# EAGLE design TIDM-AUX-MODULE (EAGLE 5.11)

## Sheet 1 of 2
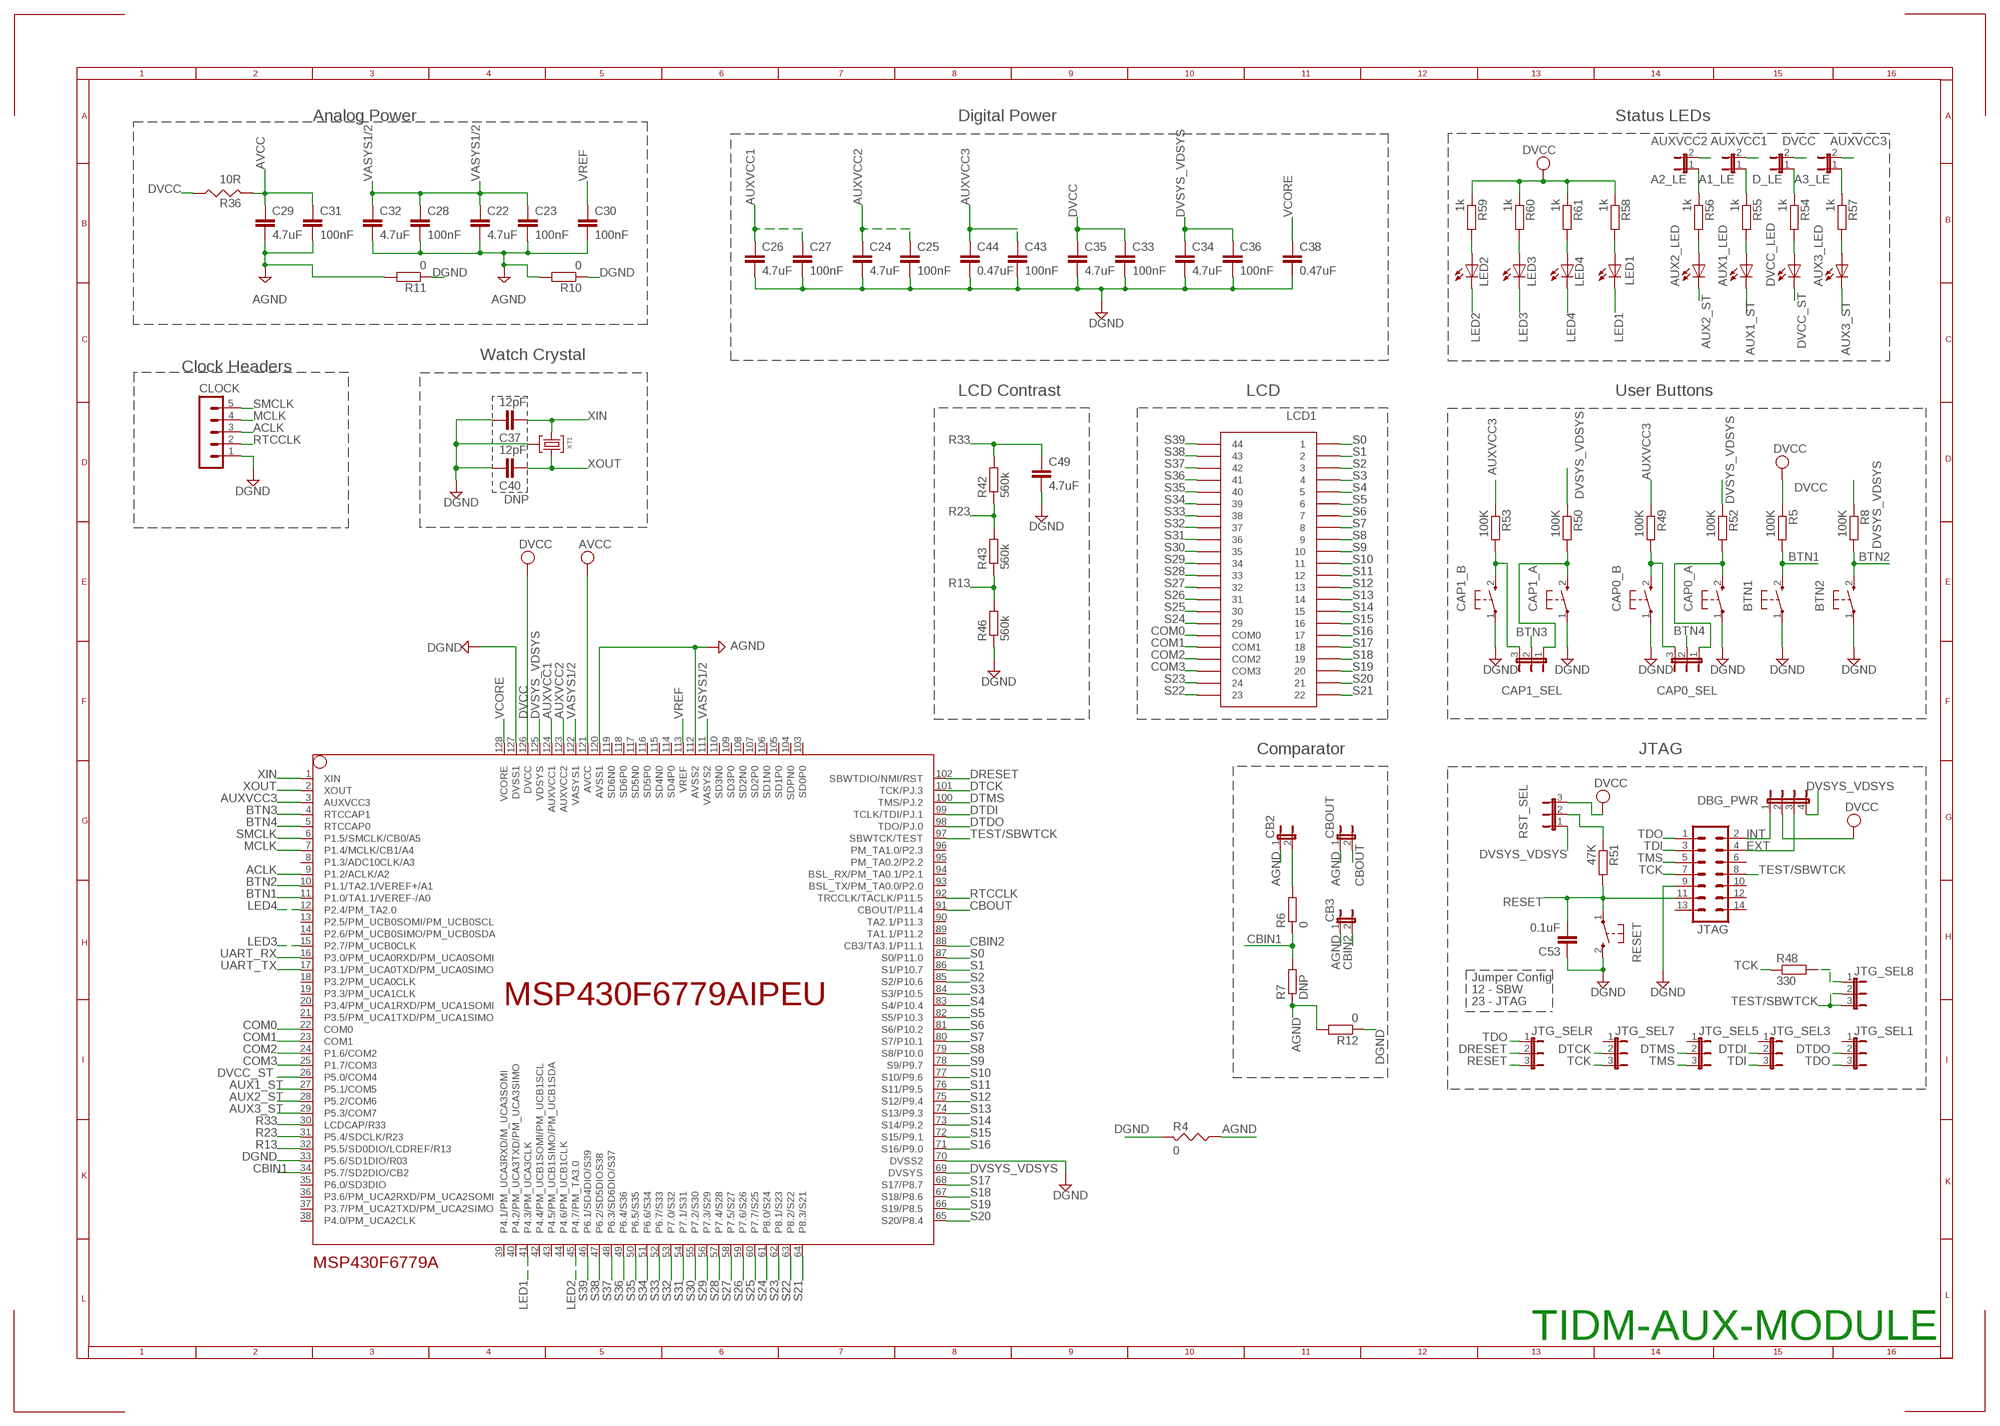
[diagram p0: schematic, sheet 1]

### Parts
A1_LE  JP1E  [JP1]
A2_LE  JP1E  [JP1]
A3_LE  JP1E  [JP1]
AUX1_LED  LED3MM  [LED3MM]
AUX2_LED  LED3MM  [LED3MM]
AUX3_LED  LED3MM  [LED3MM]
BTN1  PB  [PBTH]
BTN2  PB  [PBTH]
C22  4.7uF  C-EUC0603  [C0603]
C23  100nF  C-EUC0603  [C0603]
C24  4.7uF  C-EUC0603  [C0603]
C25  100nF  C-EUC0603  [C0603]
C26  4.7uF  C-EUC0603  [C0603]
C27  100nF  C-EUC0603  [C0603]
C28  100nF  C-EUC0603  [C0603]
C29  4.7uF  C-EUC0603  [C0603]
C30  100nF  C-EUC0603  [C0603]
C31  100nF  C-EUC0603  [C0603]
C32  4.7uF  C-EUC0603  [C0603]
C33  100nF  C-EUC0603  [C0603]
C34  4.7uF  C-EUC0603  [C0603]
C35  4.7uF  C-EUC0603  [C0603]
C36  100nF  C-EUC0603  [C0603]
C37  12pF  C-EUC0603  [C0603]
C38  0.47uF  C-EUC0603  [C0603]
C40  12pF  C-EUC0603  [C0603]
C43  100nF  C-EUC0603  [C0603]
C44  0.47uF  C-EUC0603  [C0603]
C49  4.7uF  C-EUC0603  [C0603]
C53  0.1uF  C-EUC0603  [C0603]
CAP0_A  PB  [PBTH]
CAP0_B  PB  [PBTH]
CAP0_SEL  JP2E  [JP2]
CAP1_A  PB  [PBTH]
CAP1_B  PB  [PBTH]
CAP1_SEL  JP2E  [JP2]
CB2  JP1E  [JP1]
CB3  JP1E  [JP1]
CBOUT  JP1E  [JP1]
CLOCK  MA05-1  [MA05-1]
D_LE  JP1E  [JP1]
DBG_PWR  JP4E  [JP4]
DVCC_LED  LED3MM  [LED3MM]
JTAG  ML14  [ML14]
JTG_SEL1  JP2E  [JP2]
JTG_SEL3  JP2E  [JP2]
JTG_SEL5  JP2E  [JP2]
JTG_SEL7  JP2E  [JP2]
JTG_SEL8  JP2E  [JP2]
JTG_SELR  JP2E  [JP2]
LCD1  TI_160SEG_LCD  [TI_160SEG_LCD]
LED1  LED3MM  [LED3MM]
LED2  LED3MM  [LED3MM]
LED3  LED3MM  [LED3MM]
LED4  LED3MM  [LED3MM]
MSP430F6779A  MSP430F6779AIPEU  [PEU128]
R4  0  RES0805  [R0805]
R5  100K  R-EU_R0603  [R0603]
R6  0  R-EU_R0603  [R0603]
R7  DNP  R-EU_R0603  [R0603]
R8  100K  R-EU_R0603  [R0603]
R10  0  R-EU_R0603  [R0603]
R11  0  R-EU_R0603  [R0603]
R12  0  R-EU_R0603  [R0603]
R36  10R  RES0805  [R0805]
R42  560k  R-EU_R0603  [R0603]
R43  560k  R-EU_R0603  [R0603]
R46  560k  R-EU_R0603  [R0603]
R48  330  R-EU_R0603  [R0603]
R49  100K  R-EU_R0603  [R0603]
R50  100K  R-EU_R0603  [R0603]
R51  47K  R-EU_R0603  [R0603]
R52  100K  R-EU_R0603  [R0603]
R53  100K  R-EU_R0603  [R0603]
R54  1k  R-EU_R0603  [R0603]
R55  1k  R-EU_R0603  [R0603]
R56  1k  R-EU_R0603  [R0603]
R57  1k  R-EU_R0603  [R0603]
R58  1k  R-EU_R0603  [R0603]
R59  1k  R-EU_R0603  [R0603]
R60  1k  R-EU_R0603  [R0603]
R61  1k  R-EU_R0603  [R0603]
RESET  PB  [PBTH]
RST_SEL  JP2E  [JP2]
XT1  CM200T  [CM200T]

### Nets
ACLK: CLOCK.3 MSP430F6779A.9(P1.2/ACLK/A2)
AGND: C22.2 C23.2 C28.2 C29.2 C30.2 C31.2 C32.2 CB2.1 CB3.1 CBOUT.1 MSP430F6779A.112(AVSS2) MSP430F6779A.120(AVSS1) R4.1 R7.1 R10.2 R11.2 R12.2
AUX1_ST: AUX1_LED.K(C) MSP430F6779A.27(P5.1/COM5)
AUX2_ST: AUX2_LED.K(C) MSP430F6779A.28(P5.2/COM6)
AUX3_ST: AUX3_LED.K(C) MSP430F6779A.29(P5.3/COM7)
AUXVCC1: A1_LE.2 C26.1 C27.1 MSP430F6779A.124(AUXVCC1) ; also sheet 2
AUXVCC2: A2_LE.2 C24.1 C25.1 MSP430F6779A.123(AUXVCC2) ; also sheet 2
AUXVCC3: A3_LE.2 C43.1 C44.1 MSP430F6779A.3(AUXVCC3) R49.1 R53.1 ; also sheet 2
AVCC: C29.1 C31.1 MSP430F6779A.121(AVCC) R36.2
BTN1: BTN1.2(S) MSP430F6779A.11(P1.0/TA1.1/VEREF-/A0) R5.2
BTN2: BTN2.2(S) MSP430F6779A.10(P1.1/TA2.1/VEREF+/A1) R8.2
BTN3: CAP1_SEL.2 MSP430F6779A.4(RTCCAP1)
BTN4: CAP0_SEL.2 MSP430F6779A.5(RTCCAP0)
CAP0_OP1: CAP0_B.2(S) CAP0_SEL.3 R49.2
CBIN1: MSP430F6779A.34(P5.7/SD2DIO/CB2) R6.1 R7.2
CBIN2: CB3.2 MSP430F6779A.88(CB3/TA3.1/P11.1)
CBOUT: CBOUT.2 MSP430F6779A.91(CBOUT/P11.4)
COM0: LCD1.COM0 MSP430F6779A.22(COM0)
COM1: LCD1.COM1 MSP430F6779A.23(COM1)
COM2: LCD1.COM2 MSP430F6779A.24(P1.6/COM2)
COM3: LCD1.COM3 MSP430F6779A.25(P1.7/COM3)
DGND: BTN1.1(P) BTN2.1(P) C24.2 C25.2 C26.2 C27.2 C33.2 C34.2 C35.2 C36.2 C37.2 C38.2 C40.2 C43.2 C44.2 C49.2 C53.1 CAP0_A.1(P) CAP0_B.1(P) CAP1_A.1(P) CAP1_B.1(P) CLOCK.1 JTAG.9 MSP430F6779A.33(P5.6/SD1DIO/R03) MSP430F6779A.70(DVSS2) MSP430F6779A.127(DVSS1) R4.2 R10.1 R11.1 R12.1 R46.1 RESET.2(S) XT1.P3 ; also sheet 2
DRESET: JTG_SELR.2 MSP430F6779A.102(SBWTDIO/NMI/RST)
DTCK: JTG_SEL7.2 MSP430F6779A.101(TCK/PJ.3)
DTDI: JTG_SEL3.2 MSP430F6779A.99(TCLK/TDI/PJ.1)
DTDO: JTG_SEL1.2 MSP430F6779A.98(TDO/PJ.0)
DTMS: JTG_SEL5.2 MSP430F6779A.100(TMS/PJ.2)
DVCC: C33.1 C35.1 D_LE.2 DBG_PWR.2 MSP430F6779A.126(DVCC) R5.1 R36.1 R58.1 R59.1 R60.1 R61.1 RST_SEL.3 ; also sheet 2
DVCC_ST: DVCC_LED.K(C) MSP430F6779A.26(P5.0/COM4)
DVSYS_VDSYS: C34.1 C36.1 DBG_PWR.4 MSP430F6779A.69(DVSYS) MSP430F6779A.125(VDSYS) R8.1 R50.1 R52.1 RST_SEL.1 ; also sheet 2
EXT: DBG_PWR.3 JTAG.4
INT: DBG_PWR.1 JTAG.2
LED1: LED1.K(C) MSP430F6779A.41(P4.3/PM_UCA3CLK)
LED2: LED2.K(C) MSP430F6779A.45(P4.7/PM_TA3.0)
LED3: LED3.K(C) MSP430F6779A.15(P2.7/PM_UCB0CLK)
LED4: LED4.K(C) MSP430F6779A.12(P2.4/PM_TA2.0)
MCLK: CLOCK.4 MSP430F6779A.7(P1.4/MCLK/CB1/A4)
N$1: CAP1_B.2(S) CAP1_SEL.3 R53.2
N$3: CAP1_A.2(S) CAP1_SEL.1 R50.2
N$4: AUX2_LED.A R56.2
N$6: CAP0_A.2(S) CAP0_SEL.1 R52.2
N$7: AUX1_LED.A R55.2
N$10: JTG_SEL8.1 R48.2
N$14: CB2.2 R6.2
N$16: R51.1 RST_SEL.2
N$21: LED2.A R59.2
N$23: A2_LE.1 R56.1
N$25: A1_LE.1 R55.1
N$27: LED3.A R60.2
N$29: D_LE.1 R54.1
N$30: DVCC_LED.A R54.2
N$31: A3_LE.1 R57.1
N$36: LED4.A R61.2
N$44: LED1.A R58.2
N$46: AUX3_LED.A R57.2
R13: MSP430F6779A.32(P5.5/SD0DIO/LCDREF/R13) R43.1 R46.2
R23: MSP430F6779A.31(P5.4/SDCLK/R23) R42.1 R43.2
R33: C49.1 MSP430F6779A.30(LCDCAP/R33) R42.2
RESET: C53.2 JTAG.11 JTG_SELR.3 R51.2 RESET.1(P)
RTCCLK: CLOCK.2 MSP430F6779A.92(TRCCLK/TACLK/P11.5)
S0: LCD1.1 MSP430F6779A.87(S0/P11.0)
S1: LCD1.2 MSP430F6779A.86(S1/P10.7)
S2: LCD1.3 MSP430F6779A.85(S2/P10.6)
S3: LCD1.4 MSP430F6779A.84(S3/P10.5)
S4: LCD1.5 MSP430F6779A.83(S4/P10.4)
S5: LCD1.6 MSP430F6779A.82(S5/P10.3)
S6: LCD1.7 MSP430F6779A.81(S6/P10.2)
S7: LCD1.8 MSP430F6779A.80(S7/P10.1)
S8: LCD1.9 MSP430F6779A.79(S8/P10.0)
S9: LCD1.10 MSP430F6779A.78(S9/P9.7)
S10: LCD1.11 MSP430F6779A.77(S10/P9.6)
S11: LCD1.12 MSP430F6779A.76(S11/P9.5)
S12: LCD1.13 MSP430F6779A.75(S12/P9.4)
S13: LCD1.14 MSP430F6779A.74(S13/P9.3)
S14: LCD1.15 MSP430F6779A.73(S14/P9.2)
S15: LCD1.16 MSP430F6779A.72(S15/P9.1)
S16: LCD1.17 MSP430F6779A.71(S16/P9.0)
S17: LCD1.18 MSP430F6779A.68(S17/P8.7)
S18: LCD1.19 MSP430F6779A.67(S18/P8.6)
S19: LCD1.20 MSP430F6779A.66(S19/P8.5)
S20: LCD1.21 MSP430F6779A.65(S20/P8.4)
S21: LCD1.22 MSP430F6779A.64(P8.3/S21)
S22: LCD1.23 MSP430F6779A.63(P8.2/S22)
S23: LCD1.24 MSP430F6779A.62(P8.1/S23)
S24: LCD1.29 MSP430F6779A.61(P8.0/S24)
S25: LCD1.30 MSP430F6779A.60(P7.7/S25)
S26: LCD1.31 MSP430F6779A.59(P7.6/S26)
S27: LCD1.32 MSP430F6779A.58(P7.5/S27)
S28: LCD1.33 MSP430F6779A.57(P7.4/S28)
S29: LCD1.34 MSP430F6779A.56(P7.3/S29)
S30: LCD1.35 MSP430F6779A.55(P7.2/S30)
S31: LCD1.36 MSP430F6779A.54(P7.1/S31)
S32: LCD1.37 MSP430F6779A.53(P7.0/S32)
S33: LCD1.38 MSP430F6779A.52(P6.7/S33)
S34: LCD1.39 MSP430F6779A.51(P6.6/S34)
S35: LCD1.40 MSP430F6779A.50(P6.5/S35)
S36: LCD1.41 MSP430F6779A.49(P6.4/S36)
S37: LCD1.42 MSP430F6779A.48(P6.3/SD6DIO/S37)
S38: LCD1.43 MSP430F6779A.47(P6.2/SD5DIOS38)
S39: LCD1.44 MSP430F6779A.46(P6.1/SD4DIO/S39)
SMCLK: CLOCK.5 MSP430F6779A.6(P1.5/SMCLK/CB0/A5)
TCK: JTAG.7 JTG_SEL7.3 R48.1
TDI: JTAG.3 JTG_SEL3.3
TDO: JTAG.1 JTG_SEL1.3 JTG_SELR.1
TEST/SBWTCK: JTAG.8 JTG_SEL8.2 JTG_SEL8.3 MSP430F6779A.97(SBWTCK/TEST)
TMS: JTAG.5 JTG_SEL5.3
UART_RX: MSP430F6779A.16(P3.0/PM_UCA0RXD/PM_UCA0SOMI) ; also sheet 2
UART_TX: MSP430F6779A.17(P3.1/PM_UCA0TXD/PM_UCA0SIMO) ; also sheet 2
VASYS1/2: C22.1 C23.1 C28.1 C32.1 MSP430F6779A.111(VASYS2) MSP430F6779A.122(VASYS1)
VCORE: C38.1 MSP430F6779A.128(VCORE)
VREF: C30.1 MSP430F6779A.113(VREF)
XIN: C37.1 MSP430F6779A.1(XIN) XT1.P2
XOUT: C40.1 MSP430F6779A.2(XOUT) XT1.P1
Unconnected: JTAG.6 JTAG.10 JTAG.12 JTAG.13 JTAG.14 JTG_SEL1.1 JTG_SEL3.1 JTG_SEL5.1 JTG_SEL7.1 MSP430F6779A.8(P1.3/ADC10CLK/A3) MSP430F6779A.13(P2.5/PM_UCB0SOMI/PM_UCB0SCL) MSP430F6779A.14(P2.6/PM_UCB0SIMO/PM_UCB0SDA) MSP430F6779A.18(P3.2/PM_UCA0CLK) MSP430F6779A.19(P3.3/PM_UCA1CLK) MSP430F6779A.20(P3.4/PM_UCA1RXD/PM_UCA1SOMI) MSP430F6779A.21(P3.5/PM_UCA1TXD/PM_UCA1SIMO) MSP430F6779A.35(P6.0/SD3DIO) MSP430F6779A.36(P3.6/PM_UCA2RXD/PM_UCA2SOMI) MSP430F6779A.37(P3.7/PM_UCA2TXD/PM_UCA2SIMO) MSP430F6779A.38(P4.0/PM_UCA2CLK) MSP430F6779A.39(P4.1/PM_UCA3RXD/M_UCA3SOMI) MSP430F6779A.40(P4.2/PM_UCA3TXD/PM_UCA3SIMO) MSP430F6779A.42(P4.4/PM_UCB1SOMI/PM_UCB1SCL) MSP430F6779A.43(P4.5/PM_UCB1SIMO/PM_UCB1SDA) MSP430F6779A.44(P4.6/PM_UCB1CLK) MSP430F6779A.89(TA1.1/P11.2) MSP430F6779A.90(TA2.1/P11.3) MSP430F6779A.93(BSL_TX/PM_TA0.0/P2.0) MSP430F6779A.94(BSL_RX/PM_TA0.1/P2.1) MSP430F6779A.95(PM_TA0.2/P2.2) MSP430F6779A.96(PM_TA1.0/P2.3) MSP430F6779A.103(SD0P0) MSP430F6779A.104(SDPN0) MSP430F6779A.105(SD1P0) MSP430F6779A.106(SD1N0) MSP430F6779A.107(SD2P0) MSP430F6779A.108(SD2N0) MSP430F6779A.109(SD3P0) MSP430F6779A.110(SD3N0) MSP430F6779A.114(SD4P0) MSP430F6779A.115(SD4N0) MSP430F6779A.116(SD5P0) MSP430F6779A.117(SD5N0) MSP430F6779A.118(SD6P0) MSP430F6779A.119(SD6N0)

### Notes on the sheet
- Analog Power | Digital Power | Status LEDs
- Watch Crystal
- Clock Headers
- LCD Contrast | LCD | User Buttons
- DNP
- Comparator | JTAG
- Jumper Config
- 12 - SBW
- 23 - JTAG
- TIDM-AUX-MODULE

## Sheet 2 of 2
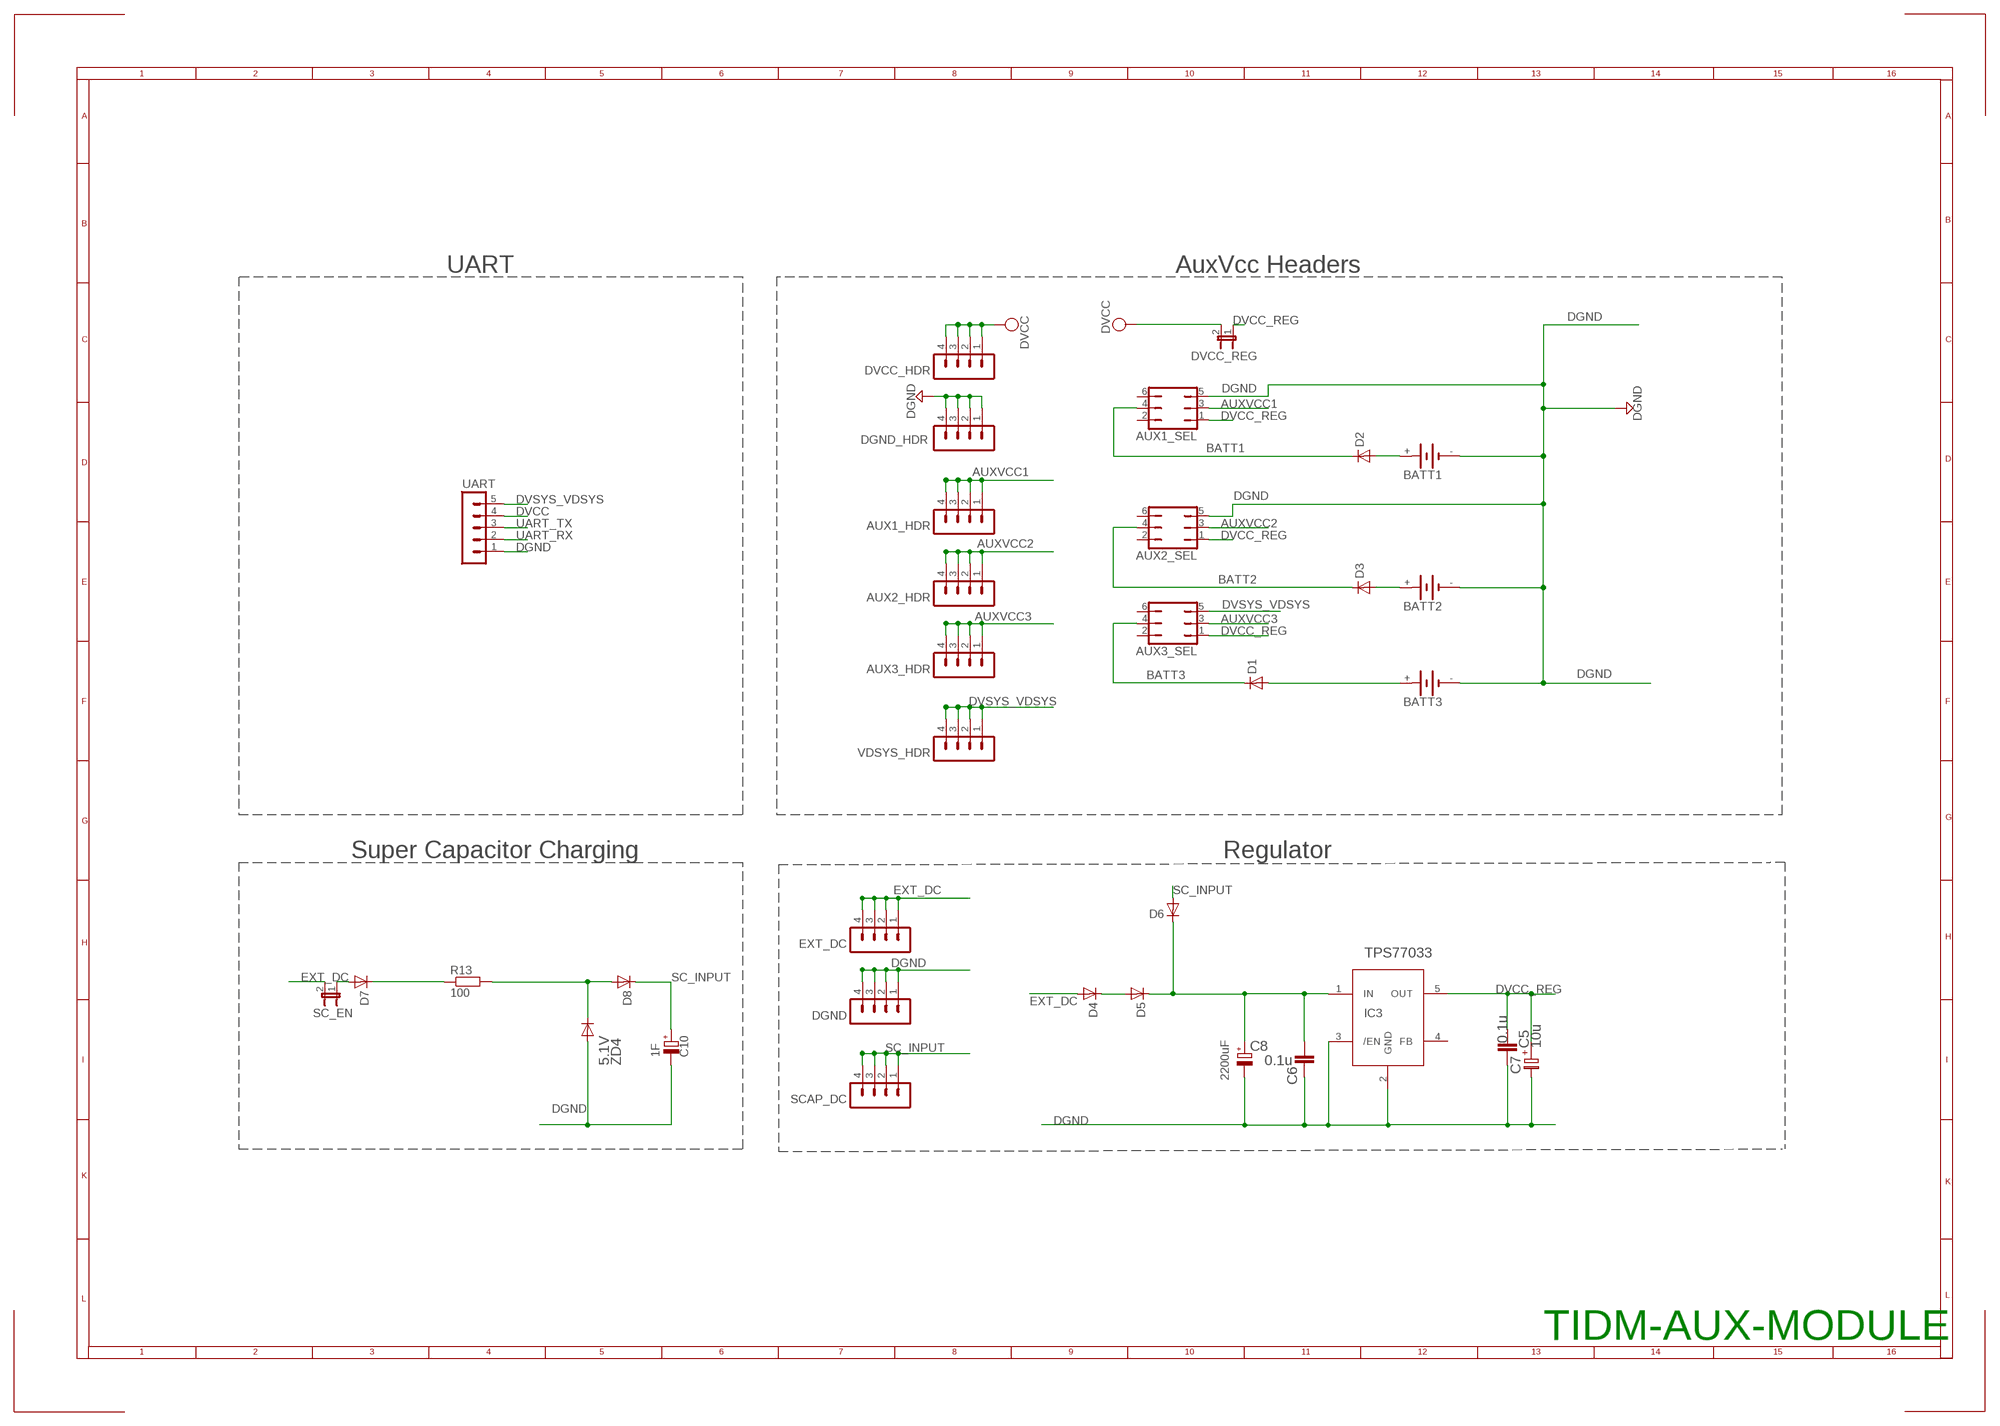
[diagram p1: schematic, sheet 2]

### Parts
AUX1_HDR  MA04-1  [MA04-1]
AUX1_SEL  JP3Q  [JP3Q]
AUX2_HDR  MA04-1  [MA04-1]
AUX2_SEL  JP3Q  [JP3Q]
AUX3_HDR  MA04-1  [MA04-1]
AUX3_SEL  JP3Q  [JP3Q]
BATT1  KS2468NO_HOLES  [KS2468_2]
BATT2  KS2468NO_HOLES  [KS2468_2]
BATT3  KS2468NO_HOLES  [KS2468_2]
C5  10u  ELKO_1210  [1210ELKO]
C6  0.1u  C-EUC0603  [C0603]
C7  0.1u  C-EUC0603  [C0603]
C8  2200uF  CPOL-EUE5-13  [E5-13]
C10  1F  CPOL-EUSUPERCAP  [C050-055X20SUPERCAP]
D1  PMLL4148  [SOD80C]
D2  PMLL4148  [SOD80C]
D3  PMLL4148  [SOD80C]
D4  PMLL4148  [SOD80C]
D5  PMLL4148  [SOD80C]
D6  PMLL4148  [SOD80C]
D7  PMLL4148  [SOD80C]
D8  PMLL4148  [SOD80C]
DGND  MA04-1  [MA04-1]
DGND_HDR  MA04-1  [MA04-1]
DVCC_HDR  MA04-1  [MA04-1]
DVCC_REG  JP1E  [JP1]
EXT_DC  MA04-1  [MA04-1]
IC3  TPS77033  TPS77001  [SOT23/5]
R13  100  R-EU_R0603  [R0603]
SC_EN  JP1E  [JP1]
SCAP_DC  MA04-1  [MA04-1]
UART  MA05-1  [MA05-1]
VDSYS_HDR  MA04-1  [MA04-1]
ZD4  5.1V  D  [SOD-80]

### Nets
AUXVCC1: AUX1_HDR.1 AUX1_HDR.2 AUX1_HDR.3 AUX1_HDR.4 AUX1_SEL.3 ; also sheet 1
AUXVCC2: AUX2_HDR.1 AUX2_HDR.2 AUX2_HDR.3 AUX2_HDR.4 AUX2_SEL.3 ; also sheet 1
AUXVCC3: AUX3_HDR.1 AUX3_HDR.2 AUX3_HDR.3 AUX3_HDR.4 AUX3_SEL.3 ; also sheet 1
BATT1: AUX1_SEL.4 D2.C
BATT2: AUX2_SEL.4 D3.C
BATT3: AUX3_SEL.4 D1.C
DGND: AUX1_SEL.5 AUX2_SEL.5 BATT1.- BATT2.- BATT3.- C5.- C6.1 C7.1 C8.- C10.2(-) DGND.1 DGND.2 DGND.3 DGND.4 DGND_HDR.1 DGND_HDR.2 DGND_HDR.3 DGND_HDR.4 IC3.2(GND) IC3.3(/EN) UART.1 ZD4.1(A) ; also sheet 1
DVCC: DVCC_HDR.1 DVCC_HDR.2 DVCC_HDR.3 DVCC_HDR.4 DVCC_REG.2 UART.4 ; also sheet 1
DVCC_REG: AUX1_SEL.1 AUX2_SEL.1 AUX3_SEL.1 C5.+ C7.2 DVCC_REG.1 IC3.5(OUT)
DVSYS_VDSYS: AUX3_SEL.5 UART.5 VDSYS_HDR.1 VDSYS_HDR.2 VDSYS_HDR.3 VDSYS_HDR.4 ; also sheet 1
EXT_DC: D4.A EXT_DC.1 EXT_DC.2 EXT_DC.3 EXT_DC.4 SC_EN.2
N$2: D4.C D5.A
N$13: D8.A R13.2 ZD4.2(K)
N$15: BATT1.+ D2.A
N$19: BATT2.+ D3.A
N$20: BATT3.+ D1.A
N$22: D7.A SC_EN.1
REG_IN: C6.2 C8.+ D5.C D6.C IC3.1(IN)
SC_INPUT: C10.1(+) D6.A D8.C SCAP_DC.1 SCAP_DC.2 SCAP_DC.3 SCAP_DC.4
SCAP_1: D7.C R13.1
UART_RX: UART.2 ; also sheet 1
UART_TX: UART.3 ; also sheet 1
Unconnected: AUX1_SEL.2 AUX1_SEL.6 AUX2_SEL.2 AUX2_SEL.6 AUX3_SEL.2 AUX3_SEL.6 IC3.4(FB)

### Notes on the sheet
- UART | AuxVcc Headers
- Super Capacitor Charging | Regulator
- TIDM-AUX-MODULE

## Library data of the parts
A1_LE A2_LE A3_LE CB2 CB3 CBOUT D_LE DVCC_REG SC_EN = jumper:JP1E: JUMPER
AUX1_HDR AUX2_HDR AUX3_HDR DGND DGND_HDR DVCC_HDR EXT_DC SCAP_DC VDSYS_HDR = custom_con-lstb:MA04-1: PIN HEADER; OC_FARNELL: unknown; OC_NEWARK: unknown
AUX1_LED AUX2_LED AUX3_LED DVCC_LED LED1-LED4 = led:LED: LED
AUX1_SEL AUX2_SEL AUX3_SEL = jumper:JP3Q: JUMPER
BATT1-BATT3 = _MSP430:KS2468
BTN1 BTN2 CAP0_A CAP0_B CAP1_A CAP1_B RESET = electricalmeter:PB: OMRON SWITCH
C5 = SMD:ELKO_1210
C6 C7 C22-C38 C40 C43 C44 C49 C53 = resistor:C-EU: CAPACITOR, European symbol
C8 = ElecMeter:CPOL-EU: POLARIZED CAPACITOR, European symbol
C10 = rcl:CPOL-EU: POLARIZED CAPACITOR, European symbol
CAP0_SEL CAP1_SEL JTG_SEL1 JTG_SEL3 JTG_SEL5 JTG_SEL7 JTG_SEL8 JTG_SELR RST_SEL = custom_jumper:JP2E: JUMPER
CLOCK UART = con-lstb:MA05-1: PIN HEADER; OC_FARNELL: unknown; OC_NEWARK: unknown
D1-D8 = FE449x EVM:PMLL4148: DIODE
DBG_PWR = jumper:JP4E: JUMPER
IC3 = flash-evk:TPS77001
JTAG = con-ml:ML14: HARTING; OC_FARNELL: unknown; OC_NEWARK: unknown
LCD1 = Personal:TI_160SEG_LCD
MSP430F6779A = Personal:MSP430F6779AIPEU: MSP430F6779IPEU
R4 R36 = _MSP430:RES
R5-R8 R10-R12 R42 R43 R46 R48-R61 = resistor:R-EU_: RESISTOR, European symbol
R13 = rcl:R-EU_: RESISTOR, European symbol
XT1 = F20xx PIR Demo & Eval:CM200T
ZD4 = SMD:D

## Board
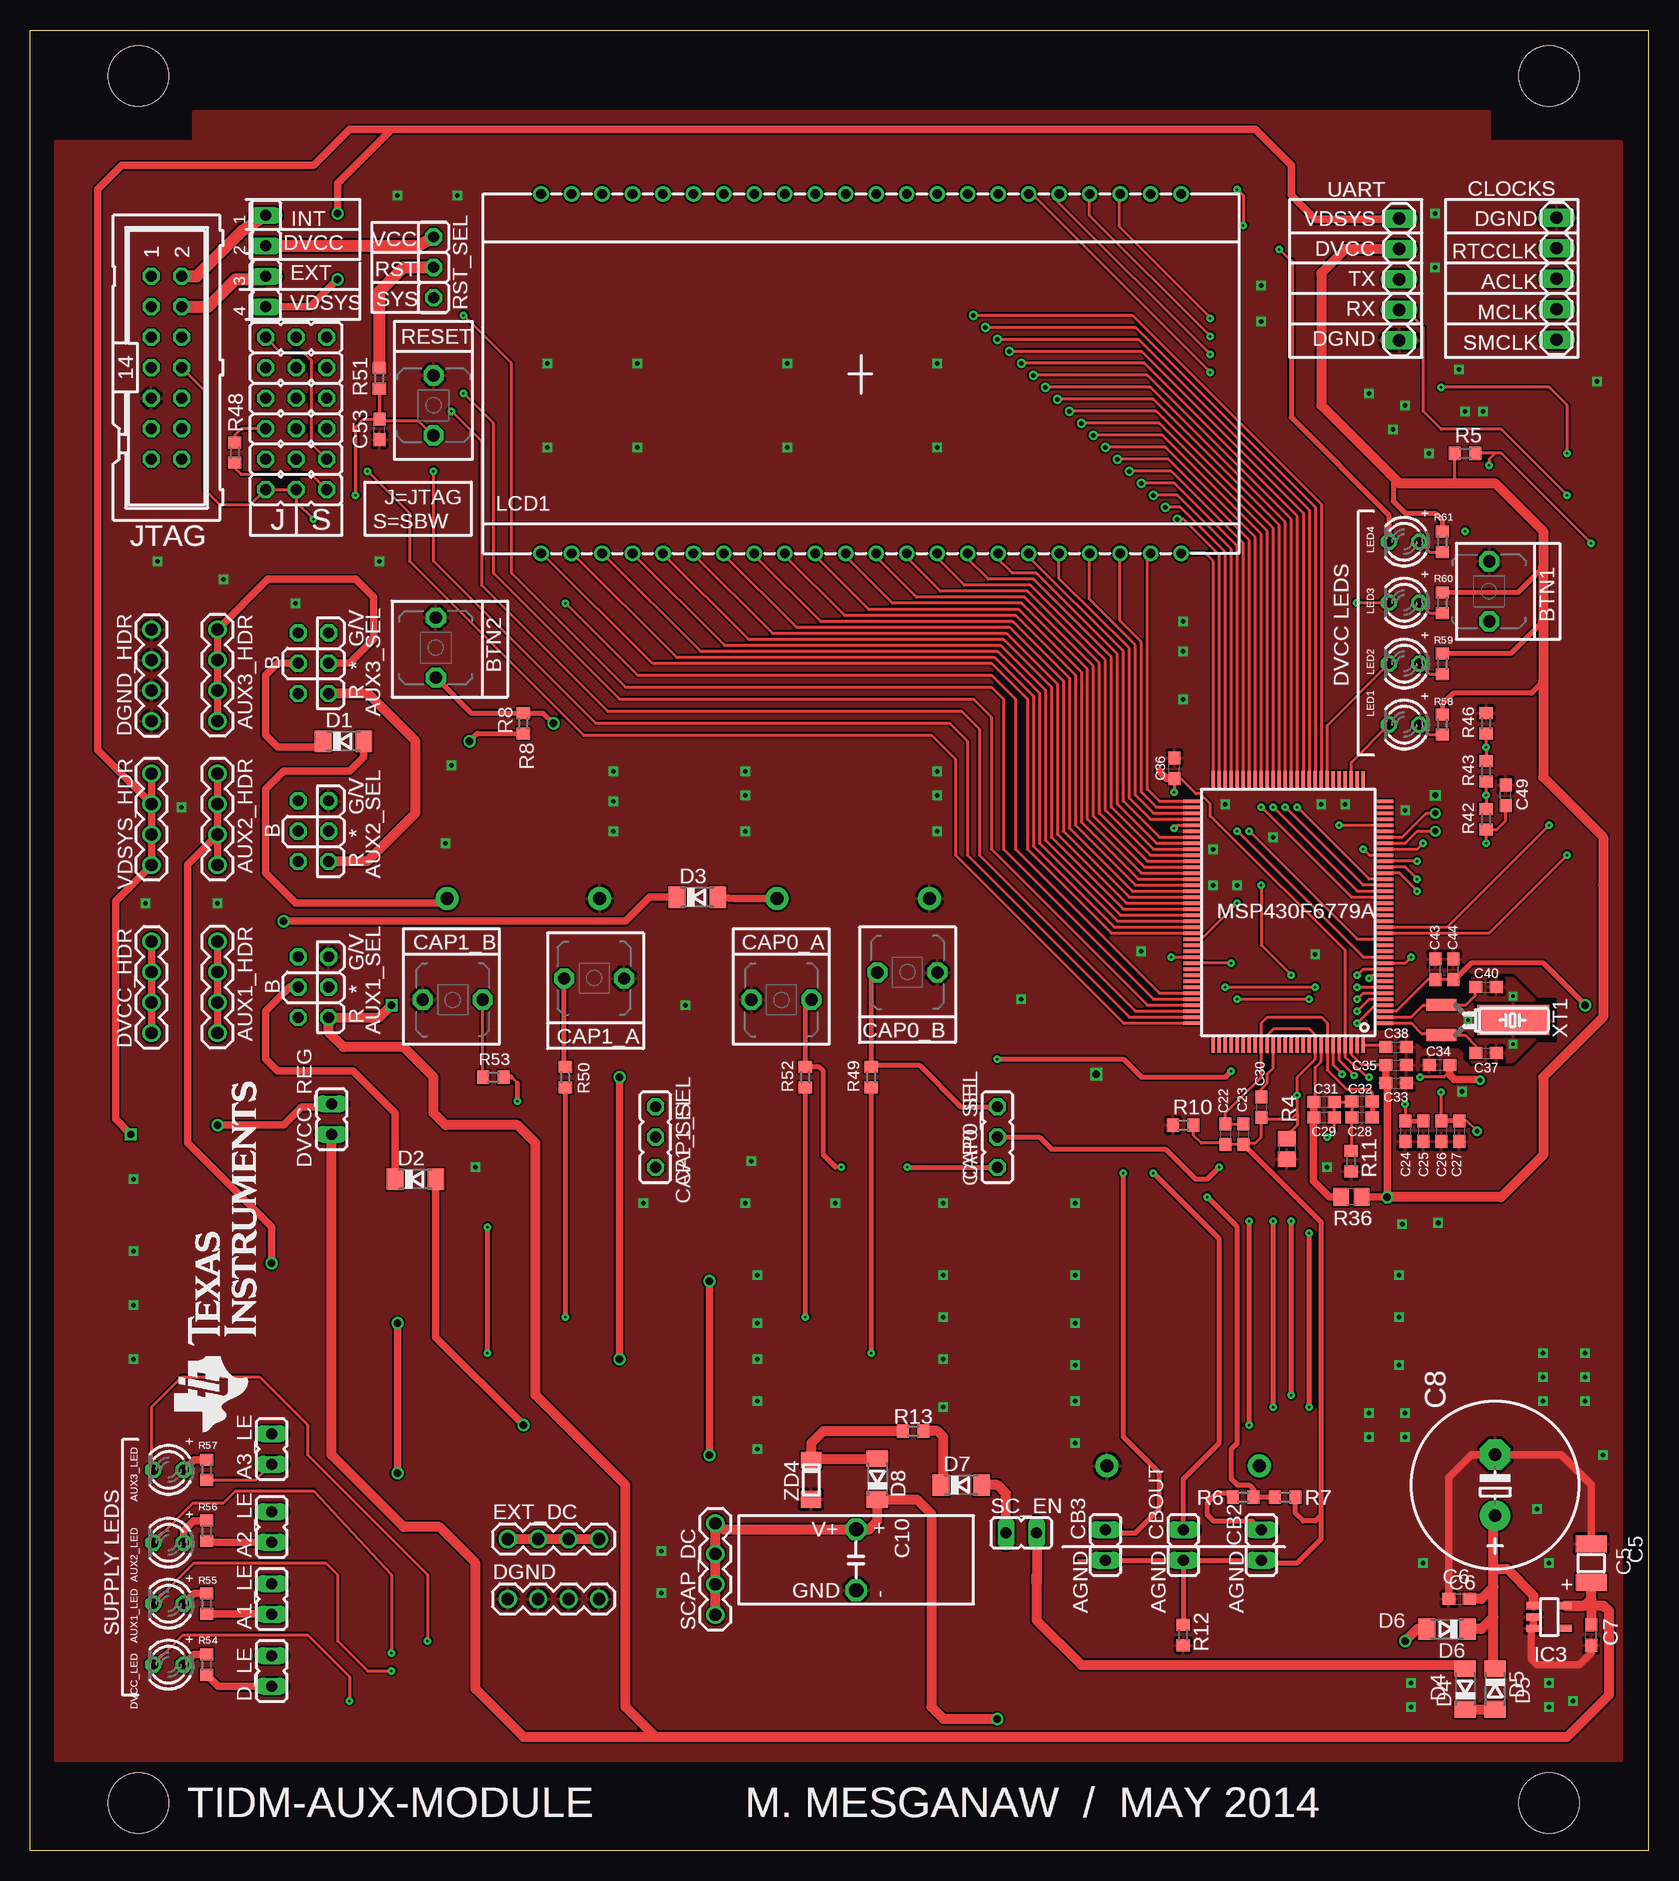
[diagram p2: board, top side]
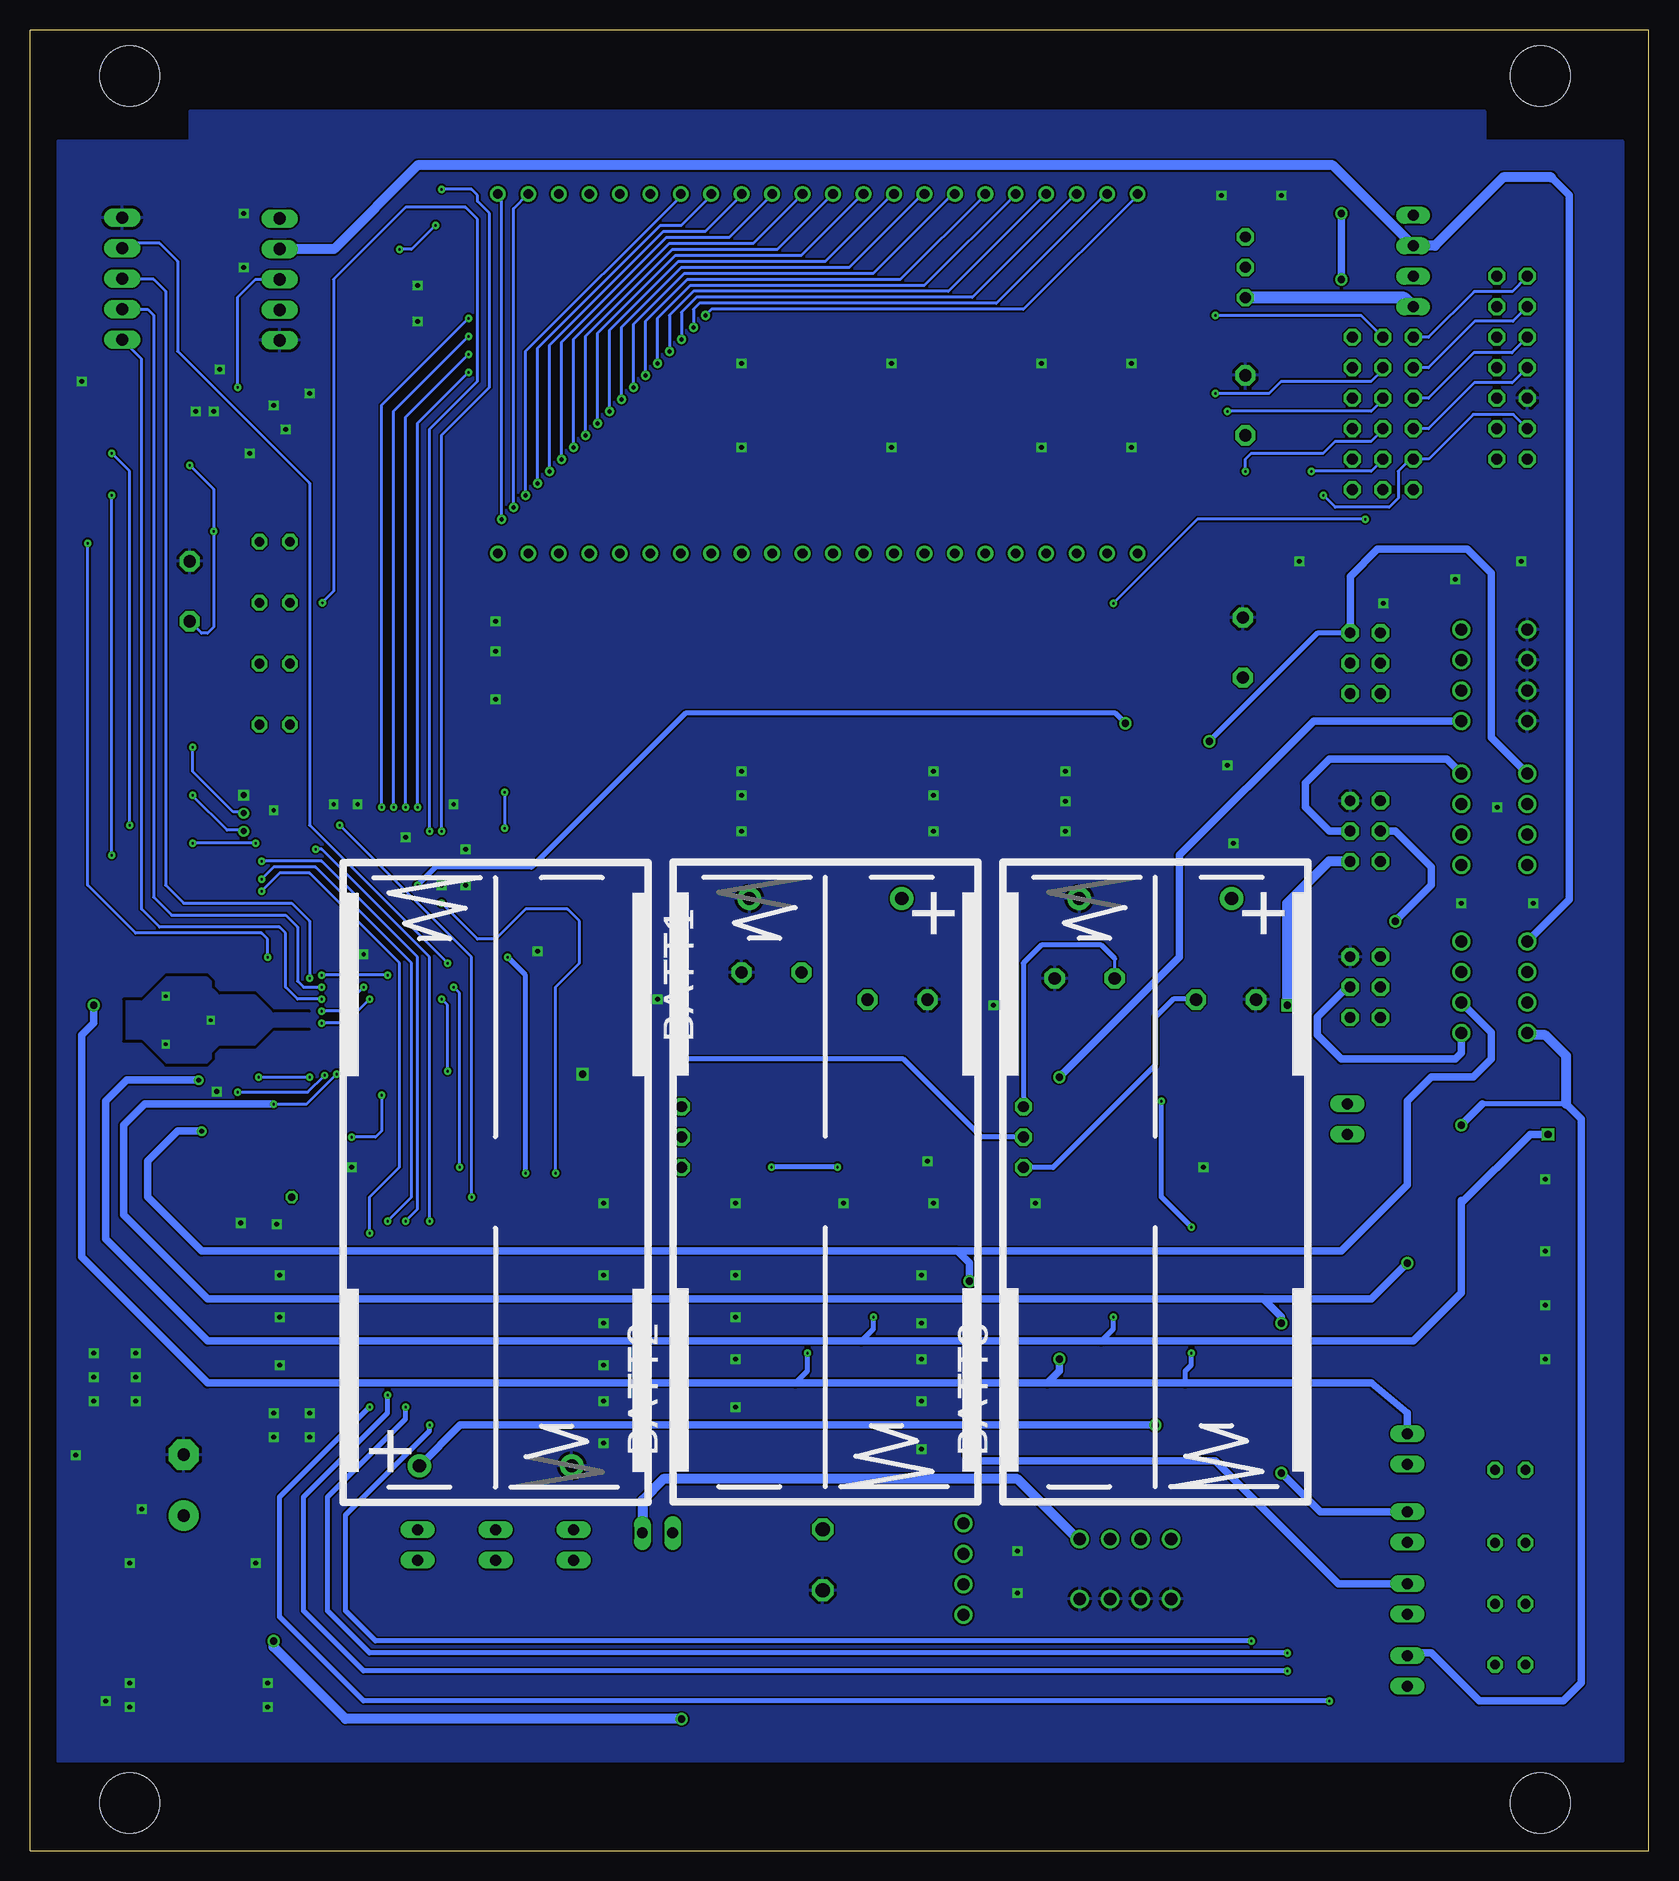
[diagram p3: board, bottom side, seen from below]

Size 134.94 x 151.79 mm. Coordinates in mm from the lower left corner, seen from the top.
Outline: 134.94,0 0,0 0,151.79 134.94,151.79 134.94,0
Copper layers (1*16): Top 0.0356mm / dielectric 1.5011mm / Bottom 0.0356mm
Design rules "typical_4pcb *": minimum track width 10mil, minimum drill 8mil, track to track 6mil, track to pad 6mil, pad to pad 6mil, via to via 6mil, smd to smd 6mil, copper to edge 15mil, drill to drill 8mil, minimum pad ring 10mil, minimum via ring 8mil, stop-mask expansion 4mil, vias tented up to drill 25mil, thermal gap 10mil
Holes 5 mm at 9.04,147.95 126.63,147.95 126.63,4 9.04,4
tRestrict: 20 lines
bRestrict: 19 lines

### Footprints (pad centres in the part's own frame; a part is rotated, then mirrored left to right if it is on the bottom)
JP1 = drill 0.914 long: 1 0,-1.27; 2 0,1.27
MA04-1 = drill 1.016 round: 1 -3.81,0; 2 -1.27,0; 3 1.27,0; 4 3.81,0
LED3MM = drill 0.813 octagon: A -1.27,0; K 1.27,0
JP3Q = drill 0.914 octagon: 1 -2.54,-1.27; 2 -2.54,1.27; 3 0,-1.27; 4 0,1.27; 5 2.54,-1.27; 6 2.54,1.27
KS2468_2 = drill 1.1 pad 1.93 round: + 24.892,-6.35; - 24.892,6.35
PBTH = drill 1.016 pad 1.676 octagon: 1 -0.001,0.001; 2 5.001,0.001
1210ELKO = smd 1.397 x 2.591: + 1.6,0; - -1.6,0
C0603 = smd 1.1 x 1: 1 -0.85,0; 2 0.85,0
E5-13 = drill 1.016 pad 2.54 round: + -2.54,0 | drill 1.016 pad 2.54 octagon: - 2.54,0
C050-055X20SUPERCAP = drill 1.2 octagon: 1 -3.81,-1.27; 2 1.27,-1.27
JP2 = drill 0.914 octagon: 1 -2.54,0; 2 0,0; 3 2.54,0
MA05-1 = drill 1.016 long: 1 -5.08,0; 2 -2.54,0; 3 0,0; 4 2.54,0; 5 5.08,0
SOD80C = smd 1.4 x 1.8: A 1.7,0; C -1.7,0
JP4 = drill 0.914 long: 1 -3.81,0; 2 -1.27,0; 3 1.27,0; 4 3.81,0
SOT23/5 = smd 0.6 x 1.2: 1 -0.95,-1.306; 2 0,-1.306; 3 0.95,-1.306; 4 0.95,1.306; 5 -0.95,1.306
ML14 = drill 0.914 octagon: 1 -7.62,-1.27; 2 -7.62,1.27; 3 -5.08,-1.27; 4 -5.08,1.27; 5 -2.54,-1.27; 6 -2.54,1.27; 7 0,-1.27; 8 0,1.27; 9 2.54,-1.27; 10 2.54,1.27; 11 5.08,-1.27; 12 5.08,1.27; 13 7.62,-1.27; 14 7.62,1.27
TI_160SEG_LCD = drill 0.8 round: 1 4.826,0; 2 7.366,0; 3 9.906,0; 4 12.446,0; 5 14.986,0; 6 17.526,0; 7 20.066,0; 8 22.606,0; 9 25.146,0; 10 27.686,0; 11 30.226,0; 12 32.766,0; 13 35.306,0; 14 37.846,0; 15 40.386,0; 16 42.926,0; 17 45.466,0; 18 48.006,0; 19 50.546,0; 20 53.086,0; 21 55.626,0; 22 58.166,0; 23 58.166,29.972; 24 55.626,29.972; 29 42.926,29.972; 30 40.386,29.972; 31 37.846,29.972; 32 35.306,29.972; 33 32.766,29.972; 34 30.226,29.972; 35 27.686,29.972; 36 25.146,29.972; 37 22.606,29.972; 38 20.066,29.972; 39 17.526,29.972; 40 14.986,29.972; 41 12.446,29.972; 42 9.906,29.972; 43 7.366,29.972; 44 4.826,29.972; COM0 45.466,29.972; COM1 48.006,29.972; COM2 50.546,29.972; COM3 53.086,29.972
PEU128 = smd 0.3 x 1.4: 1 -9,-7.8; 2 -8.5,-7.8; 3 -8,-7.8; 4 -7.5,-7.8; 5 -7,-7.8; 6 -6.5,-7.8; 7 -6,-7.8; 8 -5.5,-7.8; 9 -5,-7.8; 10 -4.5,-7.8; 11 -4,-7.8; 12 -3.5,-7.8; 13 -3,-7.8; 14 -2.5,-7.8; 15 -2,-7.8; 16 -1.5,-7.8; 17 -1,-7.8; 18 -0.5,-7.8; 19 0,-7.8; 20 0.5,-7.8; 21 1,-7.8; 22 1.5,-7.8; 23 2,-7.8; 24 2.5,-7.8; 25 3,-7.8; 26 3.5,-7.8; 27 4,-7.8; 28 4.5,-7.8; 29 5,-7.8; 30 5.5,-7.8; 31 6,-7.8; 32 6.5,-7.8; 33 7,-7.8; 34 7.5,-7.8; 35 8,-7.8; 36 8.5,-7.8; 37 9,-7.8; 38 9.5,-7.8; 65 9.5,8.3; 66 9,8.3; 67 8.5,8.3; 68 8,8.3; 69 7.5,8.3; 70 7,8.3; 71 6.5,8.3; 72 6,8.3; 73 5.5,8.3; 74 5,8.3; 75 4.5,8.3; 76 4,8.3; 77 3.5,8.3; 78 3,8.3; 79 2.5,8.3; 80 2,8.3; 81 1.5,8.3; 82 1,8.3; 83 0.5,8.3; 84 0,8.3; 85 -0.5,8.3; 86 -1,8.3; 87 -1.5,8.3; 88 -2,8.3; 89 -2.5,8.3; 90 -3,8.3; 91 -3.5,8.3; 92 -4,8.3; 93 -4.5,8.3; 94 -5,8.3; 95 -5.5,8.3; 96 -6,8.3; 97 -6.5,8.3; 98 -7,8.3; 99 -7.5,8.3; 100 -8,8.3; 101 -8.5,8.3; 102 -9,8.3 | smd 1.4 x 0.3: 39 11.3,-6; 40 11.3,-5.5; 41 11.3,-5; 42 11.3,-4.5; 43 11.3,-4; 44 11.3,-3.5; 45 11.3,-3; 46 11.3,-2.5; 47 11.3,-2; 48 11.3,-1.5; 49 11.3,-1; 50 11.3,-0.5; 51 11.3,0; 52 11.3,0.5; 53 11.3,1; 54 11.3,1.5; 55 11.3,2; 56 11.3,2.5; 57 11.3,3; 58 11.3,3.5; 59 11.3,4; 60 11.3,4.5; 61 11.3,5; 62 11.3,5.5; 63 11.3,6; 64 11.3,6.5; 103 -10.8,6.5; 104 -10.8,6; 105 -10.8,5.5; 106 -10.8,5; 107 -10.8,4.5; 108 -10.8,4; 109 -10.8,3.5; 110 -10.8,3; 111 -10.8,2.5; 112 -10.8,2; 113 -10.8,1.5; 114 -10.8,1; 115 -10.8,0.5; 116 -10.8,0; 117 -10.8,-0.5; 118 -10.8,-1; 119 -10.8,-1.5; 120 -10.8,-2; 121 -10.8,-2.5; 122 -10.8,-3; 123 -10.8,-3.5; 124 -10.8,-4; 125 -10.8,-4.5; 126 -10.8,-5; 127 -10.8,-5.5; 128 -10.8,-6
R0805 = smd 1.3 x 1.5: 1 -0.85,0; 2 0.85,0
R0603 = smd 1 x 1.1: 1 -0.85,0; 2 0.85,0
CM200T = smd 1 x 2.5: P1 -1.25,-5; P2 1.25,-5 | smd 2.5 x 6: P3 0,1
SOD-80 = smd 1.397 x 1.702: 1 1.397,-0.025; 2 -1.88,0

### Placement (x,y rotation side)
A1_LE  20.13,21 0 top
A2_LE  20.13,27 0 top
A3_LE  20.13,33.5 0 top
AUX1_HDR  15.63,72 270 top
AUX1_LED  11.55,20.61 180 top
AUX1_SEL  23.63,72 90 top
AUX2_HDR  15.63,86 270 top
AUX2_LED  11.55,25.69 180 top
AUX2_SEL  23.63,85 90 top
AUX3_HDR  15.63,98 270 top
AUX3_LED  11.55,31.77 180 top
AUX3_SEL  23.63,99 90 top
BATT1  96.13,57 270 bottom
BATT2  68.63,54.5 90 bottom
BATT3  41.13,54.5 90 bottom
BTN1  121.63,107.5 270 top
BTN2  33.83,102.8 270 top
C5  130.13,24 270 top
C6  119.13,21 0 top
C7  130.13,18 90 top
C8  122.13,30.5 90 top
C10  70.13,23 270 top
C22  99.63,59.75 270 top
C23  101.13,59.75 270 top
C24  114.63,60 270 top
C25  116.13,60 270 top
C26  117.63,60 270 top
C27  119.13,60 270 top
C28  111.03,61.12 180 top
C29  107.88,61.15 0 top
C30  102.63,62 270 top
C31  107.88,62.45 0 top
C32  111.02,62.46 180 top
C33  113.88,64 0 top
C34  117.51,65.5 180 top
C35  113.88,65.5 0 top
C36  95.38,90.25 90 top
C37  121.38,66.5 0 top
C38  113.88,67 0 top
C40  121.38,72 0 top
C43  117.13,73.5 90 top
C44  118.63,73.5 90 top
C49  123.01,88 90 top
C53  29.13,118.5 90 top
CAP0_A  60.13,70.96 0 top
CAP0_B  75.63,73.24 180 top
CAP0_SEL  80.63,59.5 90 top
CAP1_A  49.52,72.74 180 top
CAP1_B  32.74,70.96 0 top
CAP1_SEL  52.13,59.5 270 top
CB2  102.63,25.5 0 top
CB3  89.63,25.5 0 top
CBOUT  96.13,25.5 0 top
CLOCK  127.25,131.06 270 top
D1  26.13,92.5 0 top
D2  32.13,56 0 top
D3  55.63,79.5 0 top
D4  119.63,13.5 90 top
D5  122.13,13.5 270 top
D6  118.13,18.5 180 top
D7  77.63,30.5 0 top
D8  70.63,31 90 top
D_LE  20.13,15 0 top
DBG_PWR  19.64,132.53 270 top
DGND  43.63,21 0 top
DGND_HDR  10.13,98 90 top
DVCC_HDR  10.13,72 90 top
DVCC_LED  11.55,15.53 180 top
DVCC_REG  25.13,61 0 top
EXT_DC  43.63,26 0 top
IC3  126.63,19.5 270 top
JTAG  11.39,123.64 270 top
JTG_SEL1  22.18,126.18 180 top
JTG_SEL3  22.18,123.64 180 top
JTG_SEL5  22.18,121.1 180 top
JTG_SEL7  22.18,118.56 180 top
JTG_SEL8  22.18,113.48 180 top
JTG_SELR  22.18,116.02 180 top
LCD1  37.78,108.16 0 top
LED1  114.55,93.89 180 top
LED2  114.55,98.97 180 top
LED3  114.55,104.05 180 top
LED4  114.55,109.13 180 top
MSP430F6779A  105.13,78 90 top
R4  104.76,58.53 270 top
R5  119.63,116.5 0 top
R6  101.13,29.5 180 top
R7  104.63,29.5 180 top
R8  41.13,94 90 top
R10  96.13,60.5 0 top
R11  110.13,57.5 90 top
R12  96.13,18 90 top
R13  73.63,35 180 top
R36  110.14,54.51 180 top
R42  121.38,86 270 top
R43  121.38,90 270 top
R46  121.38,94 270 top
R48  17.07,116.56 270 top
R49  70.13,64.5 90 top
R50  44.63,64.5 90 top
R51  29.13,122.75 270 top
R52  64.63,64.5 90 top
R53  38.63,64.5 180 top
R54  14.73,15.53 90 top
R55  14.73,20.61 90 top
R56  14.73,26.69 90 top
R57  14.73,31.77 90 top
R58  117.73,93.89 270 top
R59  117.73,98.97 270 top
R60  117.73,104.05 270 top
R61  117.73,109.13 270 top
RESET  33.63,118 90 top
RST_SEL  33.63,132 90 top
SC_EN  82.63,26.5 270 top
SCAP_DC  57.13,23.5 90 top
UART  114.13,131 90 top
VDSYS_HDR  10.13,86 270 top
XT1  122.63,69.25 270 top
ZD4  65.13,30.7 270 top

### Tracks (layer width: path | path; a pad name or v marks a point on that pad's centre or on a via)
ACLK  (via drill 0.2)
  Top 0.254: MSP430F6779A.9 111.88,73 v111.63,72.75
  Bottom 0.254: v111.63,72.75 111.63,77.5 113.13,79 122.13,79 123.63,80.5 123.63,130 124.63,131 127.19,131 CLOCK.3 127.14,130.95
AGND  (via drill 0.2)
  Top 0.254: 87.36,24.23 CB3.1 | 102.13,24.23 102.36,24 | 105.63,61.5 v105.63,63 105.63,64.5 107.13,66 MSP430F6779A.120 107.13,68 106.63,68.5 103.63,68.5 103.13,68 MSP430F6779A.112 | 105.63,61.5 105.13,61 102.78,61 C30.2 102.63,59.5 102.13,59 101.23,59 C23.2 C22.2 99.53,59 97.63,59 96.98,59.65 R10.2 | R4.1 104.76,59.63 105.63,60.5 105.63,61.5 | v108.13,59.5 108.73,60.1 C29.2 C31.2 C32.2 C28.2 110.13,61.08 R11.2
  Top 0.406: CBOUT.1 102.13,24.23 CB2.1 | CB3.1 CBOUT.1 | C23.2 107.63,52.4 107.63,28 | 107.63,28 107.63,26 105.63,24 102.36,24 | R7.1 105.48,28.15 106.13,27.5 107.13,27.5 107.63,28 | CBOUT.1 R12.2
  Bottom 0.254: v105.63,63 105.63,60 106.13,59.5 v108.13,59.5
AUX1_ST  (via drill 0.2)
  Top 0.254: MSP430F6779A.27 114.63,82 v115.63,81 | AUX1_LED.K 13.67,24 24.63,24 25.63,23 25.63,17.5 28.13,15 v30.13,15
  Top 0.406: v105.13,38 v105.13,52.5
  Bottom 0.254: v115.63,81 114.63,82 111.13,82 103.13,74 103.13,54.5 v105.13,52.5
  Bottom 0.406: v105.13,38 105.13,36.5 112.13,29.5 112.13,20 107.13,15 v30.13,15
AUX2_ST  (via drill 0.2)
  Top 0.254: v115.63,82.5 MSP430F6779A.28 | v30.13,16.5 30.13,23 23.63,30 17.13,30 16.13,29 13.59,29 AUX2_LED.K 12.59,28
  Top 0.406: v103.63,37 v103.63,52.5
  Bottom 0.254: v103.63,52.5 102.63,53.5 102.63,74.5 110.63,82.5 v115.63,82.5
  Bottom 0.406: v103.63,37 103.63,36 110.13,29.5 110.13,20 106.63,16.5 v30.13,16.5
AUX3_ST  (via drill 0.2)
  Top 0.254: MSP430F6779A.29 111.63,83 v111.13,83.5 | v33.13,17.5 33.13,23 23.13,33 23.13,35.5 19.13,39.5 12.63,39.5 10.13,37 10.13,31.92 AUX3_LED.K
  Top 0.406: v101.63,35.5 v101.63,52.5
  Bottom 0.254: v101.63,52.5 101.63,74.5 110.63,83.5 v111.13,83.5
  Bottom 0.406: v101.63,35.5 101.63,35 108.63,28 108.63,20 106.13,17.5 v33.13,17.5
AUXVCC1  (via drill 0.2, 0.4, 0.6)
  Top 0.254: MSP430F6779A.124 109.13,65.9 v110.38,64.65 | C26.1 v117.63,63.25 | C27.1 119.78,60.85 v120.63,60
  Top 0.406: C26.1 117.63,60.5 117.98,60.85 C27.1
  Top 0.61: AUX1_HDR.1 AUX1_HDR.2 AUX1_HDR.3 AUX1_HDR.4 | v56.63,33 v56.63,47.5
  Bottom 0.254: v117.63,63.25 111.78,63.25 v110.38,64.65
  Bottom 0.61: AUX1_HDR.4 15.63,66.5 16.13,66 25.63,66 27.63,68 27.63,69.5 25.13,72 AUX1_SEL.3 | v120.63,60 122.63,60 125.13,57.5 125.13,54.5 120.63,50 57.63,50 | A1_LE.2 25.9,22.27 36.13,32.5 56.13,32.5 v56.63,33 | v56.63,47.5 56.63,49 57.63,50 | 57.63,50 25.63,50 20.13,55.5 20.13,62.5 18.13,64.5 14.63,64.5 13.13,66 13.13,68.23 AUX1_HDR.3
AUXVCC2  (via drill 0.2, 0.6)
  Top 0.254: MSP430F6779A.123 108.63,65.5 v109.38,64.75 | v114.63,62.25 C24.1
  Top 0.406: C24.1 114.63,61 114.78,60.85 C25.1
  Top 0.61: AUX2_HDR.1 AUX2_HDR.2 AUX2_HDR.3 | AUX2_HDR.3 AUX2_HDR.4 | v30.63,31.5 v30.63,44 | v20.13,49 20.13,52 13.13,59 13.13,82.23 AUX2_HDR.3
  Bottom 0.254: v114.63,62.25 111.88,62.25 v109.38,64.75
  Bottom 0.61: AUX2_SEL.3 26.63,85 28.63,87 28.63,89 26.63,91 16.82,91 AUX2_HDR.1 | v114.63,62.25 125.38,62.25 127.13,60.5 127.13,53 120.13,46 32.13,46 | A2_LE.2 27.4,28.27 v30.63,31.5 | v30.63,44 30.63,44.5 32.13,46 | 32.13,46 23.13,46 v20.13,49
AUXVCC3  (via drill 0.2, 0.6)
  Top 0.254: C43.1 117.26,72.62 | MSP430F6779A.3 113.88,70 116.53,72.65 C43.1 | C43.1 117.13,72.5 117.28,72.65 C44.1 | 40.63,64 40.13,64.5
  Top 0.406: C44.1 118.78,72.65 120.13,74 126.13,74 v129.63,70.5 | v70.13,41.5 R49.1 | v38.13,41.5 v38.13,52 | 40.13,64.5 R53.1 | v40.63,62.5 40.63,64
  Top 0.61: AUX3_HDR.4 AUX3_HDR.3 AUX3_HDR.2 AUX3_HDR.1 19.82,106 27.13,106 28.63,104.5 28.63,101 26.63,99 AUX3_SEL.3 | v49.13,41 v49.13,64.5
  Bottom 0.406: v70.13,41.5 70.13,40 71.13,39 | v40.63,62.5 40.63,54.5 v38.13,52 | v38.13,41.5 38.13,40.5 38.63,40 38.63,39
  Bottom 0.61: v129.63,70.5 129.63,69 130.63,68 130.63,49.5 120.13,39 71.13,39 50.13,39 | 50.13,39 38.63,39 23.13,39 20.13,36.5 A3_LE.2 | AUX3_HDR.4 27.94,94.19 39.13,83 39.13,74.5 v49.13,64.5 | v49.13,41 49.13,40 50.13,39
AVCC
  Top 0.254: 106.88,61.25 106.98,61.15 C29.1 | 107.13,62.5 107.08,62.45 C31.1 | MSP430F6779A.121 107.63,65.83 107.13,65.33 107.13,62.45 C31.1 | C31.1 106.93,62.45 106.88,62.5 107.03,62.65
  Top 0.406: C29.1 107.13,61.25 107.03,61.35
  Top 0.61: 107.03,61.35 C31.1 | 106.98,61.15 106.98,55.85 108.32,54.51 R36.2
BATT1
  Top 0.61: AUX1_SEL.4 21.63,72 19.63,70 19.63,66 20.63,65 26.93,65 30.43,61.5 D2.C
BATT2  (via drill 0.6)
  Top 0.61: v21.13,77.5 49.63,77.5 51.63,79.5 D3.C
  Bottom 0.61: AUX2_SEL.4 21.13,85 18.13,82 18.13,80.5 v21.13,77.5
BATT3
  Top 0.61: AUX3_SEL.4 20.63,99 19.63,98 19.63,93 20.63,92 23.93,92 D1.C
BTN1  (via drill 0.2)
  Top 0.254: MSP430F6779A.11 114.63,74 v115.13,74.5 | 122.13,116.5 122.63,116.5 v130.13,109 | 122.13,116.5 R5.2 | v121.63,115.5 121.63,116 122.13,116.5
  Bottom 0.254: v115.13,74.5 115.13,76 115.63,76.5 126.13,76.5 130.13,80.5 v130.13,109 | 122.13,103 BTN1.2 120.63,101.5 120.13,101.5 119.63,102 v119.63,110 119.63,113.5 v121.63,115.5
BTN2  (via drill 0.2, 0.6)
  Top 0.254: MSP430F6779A.10 111.13,73.5 v110.63,73 | v102.63,80.5 102.63,75.5 v105.13,73
  Top 0.406: BTN2.2 | BTN2.2 36.78,94.85 R8.2 42.78,94.85 v43.63,94
  Bottom 0.254: v105.13,73 v110.63,73
  Bottom 0.406: v102.63,80.5 101.13,82 93.13,82 80.28,94.85 44.48,94.85 v43.63,94
BTN3  (via drill 0.2)
  Top 0.254: MSP430F6779A.4 112.13,70.5 v110.63,69 | v100.63,71 v106.63,71
  Top 0.406: v100.13,65 99.63,64.5 92.63,64.5 91.13,66 v80.63,66
  Bottom 0.254: v110.63,69 108.63,69 v106.63,71 | v100.63,71 100.13,70.5 v100.13,65
  Bottom 0.406: CAP1_SEL.2 55.63,59.5 62.13,66 v80.63,66
BTN4  (via drill 0.2)
  Top 0.254: MSP430F6779A.5 111.63,71 v110.63,70 | v99.63,72 v107.13,72
  Top 0.406: v99.13,57 98.13,56 97.13,56 94.63,58.5 85.13,58.5 84.13,59.5 CAP0_SEL.2
  Bottom 0.254: v110.63,70 109.13,70 v107.13,72 | v99.63,72 99.13,71.5 v99.13,57
CAP0_OP1
  Top 0.254: R49.2 70.28,65.5
  Top 0.406: R49.2 70.13,72.74 CAP0_B.2 | CAP0_SEL.3 77.59,62.04 74.13,65.5 70.28,65.5
CBIN1  (via drill 0.2)
  Top 0.254: v109.13,85.5 MSP430F6779A.34
  Top 0.406: R7.2 R6.1 101.98,30.15 101.63,30.5 100.63,30.5 100.13,31 100.13,33.5 100.63,34 100.63,52 v98.13,54.5
  Bottom 0.254: v98.13,54.5 98.13,74.5 v109.13,85.5
CBIN2  (via drill 0.2)
  Top 0.254: MSP430F6779A.88 97.63,76 v100.63,79
  Top 0.406: v91.13,56.5 91.13,34.5 94.13,31.5 94.13,28.5 92.13,26.5 89.9,26.5 CB3.2
  Bottom 0.254: v100.63,79 97.63,76 96.13,76 93.63,78.5 90.13,78.5 89.13,77.5 89.13,74 91.13,72 v91.13,56.5
CBOUT  (via drill 0.2)
  Top 0.254: v95.13,74.5 MSP430F6779A.91
  Top 0.406: v93.63,56.5 99.13,51 99.13,34 96.13,31 CBOUT.2
  Bottom 0.406: v95.13,74.5 93.63,73 v93.63,56.5
COM0  (via drill 0.2)
  Top 0.254: MSP430F6779A.22 110.13,79.5 v102.63,87 | LCD1.COM0 83.51,138.13 v98.38,123.25
  Bottom 0.254: v102.63,87 102.63,119 v98.38,123.25
COM1  (via drill 0.2)
  Top 0.254: MSP430F6779A.23 110.63,80 v103.63,87 | v98.38,124.75 98.38,124.77 85.75,137.41 85.75,138.09 LCD1.COM1
  Bottom 0.254: v103.63,87 103.63,119.5 v98.38,124.75
COM2  (via drill 0.2)
  Top 0.254: MSP430F6779A.24 111.13,80.5 v104.63,87 | LCD1.COM2 88.33,136.31 v98.38,126.25
  Bottom 0.254: v104.63,87 104.63,120 v98.38,126.25
COM3  (via drill 0.2)
  Top 0.254: MSP430F6779A.25 111.63,81 v105.63,87 | v98.38,127.75 98.38,127.82 90.83,135.37 90.83,138.09 LCD1.COM3
  Bottom 0.254: v105.63,87 105.63,120.5 v98.38,127.75
DGND  (via drill 0.3, 0.36, 0.4, 0.5, 0.6)
  Top 0.254: BTN2.1 33.83,102.7 33.63,102.5
  Top 0.61: C7.1 130.13,16.5 129.13,15.5 125.63,15.5 125.13,16 125.13,18.36 IC3.3 IC3.2 | C5.- 130.13,30.5 127.63,33 122.17,33 C8.- 122.09,33 120.13,33 118.28,31.15 C6.1
  other vias: 99.63,87.25 117.13,88 130.63,122.5 92.63,75 121.13,120 111.63,121.5 88.88,64.75 119.88,69.25 123.63,71.25 123.63,67.25 114.63,86.75 107.63,87.25 96.13,102.5 96.13,100 75.63,124 63.13,124 50.63,124 114.38,52.25 117.38,52.35 75.63,117 63.13,117 50.63,117 119.38,63.3 116.63,116.5 113.63,118.5 114.63,120.5 43.13,124 43.13,117 29.13,107.5 10.63,107.5 22.13,104 34.63,84 48.63,85 96.13,96 59.63,90 75.63,90 54.63,70.5 82.63,71 59.63,54 67.13,54 76.13,54 87.13,54 51.13,54 30.63,138 35.63,138 8.63,50 15.63,79 9.63,79 16.13,106 37.13,57 60.13,57.5 114.13,48 87.13,48 76.13,48 60.63,48 60.63,44 60.63,41 60.63,37.5 60.63,33.5 76.13,44.5 76.13,41 76.13,37 87.13,44 87.13,40.5 87.13,37.5 87.13,34 114.13,44.5 114.13,40.5 126.13,39.5 126.13,37.5 129.63,37.5 111.63,34.5 129.63,39.5 111.63,36.5 114.63,36.5 126.13,41.5 114.63,34.5 129.63,41.5 52.63,25 52.63,21.5 8.63,45.5 8.63,41 102.63,130.5 102.63,127.5 117.13,136.5 119.13,123.5 117.13,132 48.63,90 35.13,90.5 12.63,87 8.63,56 98.63,80.5 100.63,80.5 98.63,83.5 103.63,84.5 109.63,87.25 107.13,74.75 108.13,57 119.63,120 115.13,12 115.13,14 126.63,12 126.63,14 116.13,24 131.13,33 126.63,24 128.63,12.5 125.63,28.5 59.63,85 75.63,85 48.63,87.5 59.63,88 75.63,88
  pour Top: 2.13,142.5 13.63,142.5 13.63,145 121.63,145 121.63,142.5 132.63,142.5 132.63,7.5 2.13,7.5
  pour Bottom: 2.13,142.5 13.63,142.5 13.63,145 121.63,145 121.63,142.5 132.63,142.5 132.63,7.5 2.13,7.5
DRESET  (via drill 0.2)
  Top 0.254: MSP430F6779A.102 91.13,69 77.13,83 77.13,91 75.13,93 46.13,93 31.63,107.5 31.63,111.5 v28.13,115
  Bottom 0.254: JTG_SELR.2 22.18,115.95 23.13,115 v28.13,115
DTCK  (via drill 0.2)
  Top 0.254: MSP430F6779A.101 91.63,69.5 78.13,83 78.13,92.5 76.63,94 47.13,94 33.63,107.5 v33.63,115
  Bottom 0.254: JTG_SEL7.2 22.18,118.45 23.13,117.5 26.13,117.5 27.13,116.5 33.13,116.5 33.63,116 v33.63,115
DTDI  (via drill 0.2)
  Top 0.254: MSP430F6779A.99 93.13,70.5 80.13,83.5 80.13,94.5 78.63,96 49.13,96 38.63,106.5 38.63,119 v36.13,121.5
  Bottom 0.254: JTG_SEL3.2 22.18,123.45 23.13,122.5 30.63,122.5 31.63,121.5 v36.13,121.5
DTDO  (via drill 0.2)
  Top 0.254: MSP430F6779A.98 93.63,71 81.13,83.5 81.13,96 80.13,97 49.63,97 40.13,106.5 40.13,124 v36.13,128
  Bottom 0.254: v36.13,128 24,128 JTG_SEL1.2
DTMS  (via drill 0.2)
  Top 0.254: MSP430F6779A.100 92.13,70 79.13,83 79.13,93.5 77.63,95 49.63,95 49.13,95 48.13,95 37.63,105.5 37.63,117.5 v35.13,120
  Bottom 0.254: JTG_SEL5.2 22.18,120.95 23.13,120 v35.13,120
DVCC  (via drill 0.6)
  Top 0.254: MSP430F6779A.126 110.13,66.4 111.03,65.5 C35.1 | 113.38,114.75 113.63,114.5 | R5.1 118.78,114.15 118.63,114
  Top 0.3: 131.13,80.5 130.98,80.35
  Top 0.406: 112.63,64 C33.1 113.13,63.9 | R60.1 124.03,104.9 126.13,107 | R59.1 123.45,99.82 126.13,102.5 | R58.1 117.73,95.59 118.63,96.5 125.13,96.5 126.13,97.5 | R61.1 117.73,110.91 117.13,111.5 114.63,111.5 113.63,112.5 113.63,114.5
  Top 0.61: 113.13,63.9 v113.13,54.5 R36.1 | C33.1 C35.1 | DVCC_HDR.1 DVCC_HDR.2 DVCC_HDR.3 DVCC_HDR.4 | v15.63,60.5 21.13,60.5 22.63,62 24.86,62 DVCC_REG.2
  Top 0.679: 122.68,54.54 122.63,54.5
  Top 0.813: 122.68,54.54 126.13,58 126.13,64.5 131.13,69.5 131.13,80.5 131.13,84.5 126.13,89.5 126.13,97.5 126.13,102.5 126.13,107 126.13,110 122.13,114 118.63,114 114.13,114 113.38,114.75 107.63,120.5 107.63,131.54 109.63,133.54 UART.4 | R36.1 | 113.18,54.54 v113.13,54.5 122.63,54.5
  Top 1.016: DBG_PWR.2 32.39,133.8 RST_SEL.3
  Bottom 0.406: 6.9,62.27 13.86,62.27
  Bottom 0.61: 8.13,139.5 6.63,138 6.63,79.31 DVCC_HDR.4 | 6.9,62.27 5.63,61 5.63,14 7.13,12.5 14.13,12.5 18.13,16.5 19.9,16.5 D_LE.2 | 13.86,62.27 v15.63,60.5
  Bottom 0.813: UART.4 109.59,133.54 102.63,140.5 26.34,140.5 DBG_PWR.2 17.83,133.8 12.13,139.5 8.13,139.5 | 6.9,62.27 6.9,66.27 8.63,68 9.94,68 DVCC_HDR.1
DVCC_REG  (via drill 0.6)
  Top 0.813: 130.13,21 129.58,20.45 IC3.5 131.18,20.45 131.63,20 131.63,13 128.13,9.5 52.13,9.5 | 130.13,21 C5.+ | 130.13,21 C7.2 | 52.13,9.5 41.13,9.5 37.13,13.5 37.13,24 34.13,27 31.13,27 25.13,33 DVCC_REG.1 | 52.13,9.5 49.63,12 49.63,30.5 42.13,38 42.13,59 40.63,60.5 34.63,60.5 33.63,61.5 33.63,64.5 31.13,67 26.13,67 24.9,68.23 AUX1_SEL.1 29.09,69.46 v30.13,70.5 | AUX3_SEL.1 28.17,96.46 32.13,92.5 32.13,86.5 28.13,82.5 24.94,82.5 AUX2_SEL.1
  Bottom 0.813: v30.13,70.5 30.13,79 26.63,82.5 24.94,82.5 AUX2_SEL.1
DVCC_ST  (via drill 0.2)
  Top 0.254: MSP430F6779A.26 114.13,81.5 v115.63,80 | v26.63,12.5 26.63,14.5 23.13,18 12.75,18 DVCC_LED.K
  Top 0.406: v106.63,37 v106.63,51.5
  Bottom 0.254: v115.63,80 114.13,81.5 111.63,81.5 104.13,74 104.13,57 106.63,54.5 v106.63,51.5
  Bottom 0.406: v106.63,37 114.13,29.5 114.13,19.5 107.13,12.5 v26.63,12.5
DVSYS_VDSYS  (via drill 0.2, 0.4, 0.6)
  Top 0.254: v95.38,88.25 C36.1 95.41,89.38 95.93,89.38 97.18,88.13 97.53,88.13 98.4,87.27 98.4,86.25 99.13,85.51 99.13,85.5 109.63,75.07 MSP430F6779A.125 109.63,66.15 111.48,64.5 v111.63,64.5 | MSP430F6779A.69 95.63,85.5 v95.38,85.25 | v115.88,64.5 117.86,64.5 118.36,65
  Top 0.406: v44.63,44.5 R50.1 | v64.63,44.5 R52.1 | R8.1 37.28,93.15 v36.63,92.5
  Top 0.61: VDSYS_HDR.2 VDSYS_HDR.1 | VDSYS_HDR.2 VDSYS_HDR.3 VDSYS_HDR.4 7.13,79.19 7.13,61 v8.4,59.73 | DBG_PWR.4 23.35,128.72 v25.63,131 | VDSYS_HDR.2 5.63,91.77 5.63,138.5 7.63,140.5 23.63,140.5 26.63,143.5 30.13,143.5 | C36.1 94.73,89.4 94.13,90 | UART.5 114.05,136 107.13,136 105.13,138 105.13,140.5 102.13,143.5 30.13,143.5 | v25.63,136.5 25.63,139 30.13,143.5 | C34.1 118.36,65 118.36,64.67 118.73,64.3 120.83,64.3 v120.88,64.25
  Bottom 0.254: v95.38,88.25 v95.38,85.25 | v115.88,64.5 v111.63,64.5 | AUX3_SEL.5 24.94,101.5
  Bottom 0.406: v44.63,44.5 44.63,43.5 45.63,42.5 | v64.63,44.5 64.63,43.5 65.63,42.5 | 24.94,101.5 27.63,101.5 v36.63,92.5
  Bottom 0.61: AUX3_SEL.5 24.9,106.23 22.63,108.5 15.13,108.5 13.13,106.5 13.13,92.81 VDSYS_HDR.1 | v25.63,136.5 v25.63,131 | v120.88,64.25 126.88,64.25 128.63,62.5 128.63,51 120.13,42.5 65.63,42.5 45.63,42.5 19.63,42.5 15.63,46.5 15.63,54 | 15.63,54 15.63,54.23 | v8.4,59.73 9.9,59.73 15.63,54
  Bottom 1.016: RST_SEL.1 20.38,129.46 DBG_PWR.4
EXT
  Top 1.016: JTAG.4 14.85,128.72 17.13,131 19.38,131 DBG_PWR.3
EXT_DC
  Top 0.813: 83.9,22.3 83.9,19.23 87.63,15.5 119.33,15.5 D4.A | 83.9,22.3 83.9,23 | 83.9,22.3 83.93,22.3 83.93,26.5 SC_EN.2 | EXT_DC.1 EXT_DC.2 EXT_DC.3 EXT_DC.4
  Bottom 0.813: SC_EN.2 83.9,29.23 82.13,31 52.63,31 47.63,26 EXT_DC.4
INT
  Top 1.016: JTAG.2 13.89,131.26 17.7,135.07 DBG_PWR.1
LED1
  Top 0.254: MSP430F6779A.41 110.13,90.74 LED1.K
LED2
  Top 0.254: MSP430F6779A.45 108.13,93.82 LED2.K
LED3  (via drill 0.2)
  Top 0.254: v101.63,85 110.63,76 MSP430F6779A.15 | v110.58,104.05 LED3.K
  Bottom 0.254: v101.63,85 101.63,118.5 97.63,122.5 97.63,136 98.63,137 103.63,137 109.63,131 109.63,105 v110.58,104.05
LED4  (via drill 0.2)
  Top 0.254: v100.63,85 111.13,74.5 MSP430F6779A.12 | v104.13,133.5 105.13,132.5 | v101.13,135.5 101.13,138 v100.63,138.5
  Top 0.406: LED4.K 113.28,111.35 105.13,119.5 105.13,132.5
  Bottom 0.254: v100.63,85 100.63,118 96.63,122 96.63,136.5 97.63,137.5 97.63,138 98.13,138.5 v100.63,138.5 | v104.13,133.5 103.13,133.5 v101.13,135.5
MCLK  (via drill 0.2)
  Top 0.254: v110.63,72 MSP430F6779A.7
  Bottom 0.254: v110.63,72 112.13,72 112.63,72.5 112.63,77 113.63,78 123.13,78 124.63,79.5 124.63,128 125.13,128.5 127.23,128.5 CLOCK.4 127.02,128.3
N$1
  Top 0.254: CAP1_B.2 37.74,64.54 R53.2
  Bottom 0.254: CAP1_B.2 37.78,71
  Bottom 0.406: CAP1_SEL.3 49.67,56.96 41.13,65.5 41.13,69.5 39.63,71 37.78,71
N$2
  Top 0.813: D4.C D5.A
N$3
  Top 0.254: R50.2 44.52,65.46
  Top 0.406: 44.52,65.46 CAP1_A.2
  Bottom 0.254: CAP1_A.2 44.52,74.39
  Bottom 0.406: 44.52,74.39 45.63,75.5 50.63,75.5 52.13,74 CAP1_SEL.1
N$4
  Top 0.61: AUX2_LED.A 12.82,26.69 13.63,27.5 14.69,27.5 R56.2
N$6  (via drill 0.2)
  Top 0.254: v73.13,57 73.17,56.96 | v67.63,57 67.13,57
  Top 0.406: CAP0_A.2 64.63,70.46 R52.2 65.78,65.35 66.13,65 66.13,58 67.13,57 | 73.17,56.96 CAP0_SEL.1
  Bottom 0.406: v67.63,57 v73.13,57
N$7
  Top 0.61: R55.2 13.67,21.46 AUX1_LED.A
N$10
  Top 0.254: JTG_SEL8.1 23.45,114.75 17.6,114.75 17.07,115.28 R48.2
N$13
  Top 0.813: R13.2 66.13,35 65.13,34 ZD4.2 65.25,32.7 D8.A
N$14
  Top 0.254: 100.13,29.85 R6.2 | 101.9,27.5 CB2.2
  Top 0.406: 100.13,29.85 98.98,29.85 98.13,29 98.13,28 98.63,27.5 101.9,27.5
N$15  (via drill 0.6)
  Top 0.61: D2.A 33.83,42.8 v41.13,35.5
  Bottom 0.61: v41.13,35.5 99.09,35.5 BATT1.+
N$16
  Top 1.016: R51.1 29.13,130 31.13,132 RST_SEL.2
N$19
  Top 0.61: BATT2.+ 58.72,79.39 D3.A
N$20
  Top 0.61: D1.A 27.83,91.2 26.63,90 21.13,90 19.63,88.5 19.63,81.5 22.13,79 34.39,79 BATT3.+
N$21
  Top 0.254: R59.2 116.67,98.12 LED2.A
N$22
  Top 0.813: SC_EN.1 81.36,29.77 80.63,30.5 D7.A
N$23
  Top 0.61: A2_LE.1 15.62,25.73 R56.1
N$25
  Top 0.61: R55.1 20.1,19.76 A1_LE.1
N$27
  Top 0.254: R60.2 116.67,103.2 LED3.A
N$29
  Top 0.61: D_LE.1 15.68,13.73 R54.1
N$30
  Top 0.61: R54.2 13.67,16.38 DVCC_LED.A
N$31
  Top 0.254: R57.1 18.82,30.92 A3_LE.1
N$36
  Top 0.254: R61.2 116.67,108.28 LED4.A
N$44
  Top 0.254: R58.2 116.67,93.04 LED1.A
N$46
  Top 0.61: R57.2 13.67,32.62 AUX3_LED.A
R13  (via drill 0.2, 0.5)
  Top 0.254: MSP430F6779A.32 114.38,84.5 115.88,86 115.88,86.01 116.38,86.5 v117.13,86.5 | R46.2 v121.38,92 R43.1
  Bottom 0.254: v121.38,92 121.38,89.98 118,86.61 117.24,86.61 v117.13,86.5
R23  (via drill 0.2, 0.5)
  Top 0.254: MSP430F6779A.31 114.63,84 115.63,85 v117.13,85 | R43.2 v121.38,88 R42.1
  Bottom 0.254: v121.38,88 121.38,87.95 118.51,85.08 117.21,85.08 v117.13,85
R33  (via drill 0.2)
  Top 0.254: MSP430F6779A.30 115.63,83.5 v116.13,84 | v121.38,84 R42.2 122.28,85.15 123.01,85.88 C49.1
  Bottom 0.254: v116.13,84 v121.38,84
REG_IN
  Top 0.813: D5.C 121.98,15.35 121.98,19.5 | 121.98,19.5 121.98,22 | 121.98,22 121.98,23.5 | 121.98,23.5 121.98,27.81 C8.+ | IC3.1 125.33,21.31 123.13,23.5 121.98,23.5 | D6.C 120.98,18.5 121.98,19.5 | C6.2 120.98,21 121.98,22
RESET  (via drill 0.2)
  Top 0.254: C53.2 29.12,119.75 | RESET.1 33.6,118 32.37,119.24 29.25,119.24 C53.2 | C53.2 27.78,119.35 27.13,118.7 27.13,118
  Top 0.305: C53.2 R51.2 | v27.13,113 27.13,118
  Bottom 0.254: v27.13,113 26.13,112 21.63,112 20.88,112.75 20.88,115 19.86,116.02 JTG_SELR.3 18.36,116.02 14.64,119.74 | JTAG.11 10.12,118.58 11.28,119.74 14.64,119.74 | 14.64,119.74 14.64,119.75
RTCCLK  (via drill 0.2 pad 0.25)
  Top 0.254: v100.13,74 MSP430F6779A.92
  Bottom 0.254: v100.13,74 111.63,85.5 111.63,114 122.63,125 122.63,132.5 124.13,134 126.86,134 CLOCK.2
S0
  Top 0.254: MSP430F6779A.87 90.13,76.5 83.13,83.5 83.13,96 80.13,99 51.86,99 42.71,108.16 LCD1.1
S1
  Top 0.254: MSP430F6779A.86 90.38,77 83.63,83.75 83.63,96.25 80.38,99.5 53.88,99.5 45.23,108.16 LCD1.2
S2
  Top 0.254: MSP430F6779A.85 90.63,77.5 84.13,84 84.13,96.5 80.63,100 55.88,100 47.73,108.16 LCD1.3
S3
  Top 0.254: MSP430F6779A.84 90.88,78 84.63,84.25 84.63,96.75 80.88,100.5 57.88,100.5 LCD1.4
S4
  Top 0.254: MSP430F6779A.83 91.13,78.5 85.13,84.5 85.13,97 81.13,101 59.88,101 52.77,108.12 LCD1.5
S5
  Top 0.254: MSP430F6779A.82 91.38,79 85.63,84.75 85.63,97.25 81.38,101.5 61.88,101.5 55.31,108.08 LCD1.6
S6
  Top 0.254: MSP430F6779A.81 91.63,79.5 86.13,85 86.13,97.5 81.63,102 63.88,102 57.85,108.04 LCD1.7
S7
  Top 0.254: MSP430F6779A.80 91.88,80 86.63,85.25 86.63,97.75 81.88,102.5 65.88,102.5 60.39,108 LCD1.8
S8
  Top 0.254: MSP430F6779A.79 92.13,80.5 87.13,85.5 87.13,98 82.13,103 67.88,103 62.93,107.96 LCD1.9
S9
  Top 0.254: MSP430F6779A.78 92.38,81 87.63,85.75 87.63,98.25 82.38,103.5 69.88,103.5 65.47,107.92 LCD1.10
S10
  Top 0.254: MSP430F6779A.77 92.63,81.5 88.13,86 88.13,98.5 82.63,104 71.88,104 68.01,107.88 LCD1.11
S11
  Top 0.254: MSP430F6779A.76 92.88,82 88.63,86.25 88.63,98.75 82.88,104.5 73.88,104.5 70.55,107.84 LCD1.12
S12
  Top 0.254: MSP430F6779A.75 93.13,82.5 89.13,86.5 89.13,99 83.13,105 75.88,105 73.09,107.82 LCD1.13
S13
  Top 0.254: MSP430F6779A.74 93.38,83 89.63,86.75 89.63,99.25 83.38,105.5 77.88,105.5 75.63,107.76 LCD1.14
S14
  Top 0.254: MSP430F6779A.73 93.63,83.5 90.13,87 90.13,99.5 83.63,106 79.88,106 78.17,107.74 LCD1.15
S15
  Top 0.254: MSP430F6779A.72 93.88,84 90.63,87.25 90.63,99.75 83.88,106.5 81.88,106.5 80.71,107.7 LCD1.16
S16
  Top 0.254: MSP430F6779A.71 94.13,84.5 91.13,87.5 91.13,100 83.25,107.91 LCD1.17
S17
  Top 0.254: MSP430F6779A.68 93.38,86 91.63,87.75 91.63,100.25 85.79,106.05 LCD1.18
S18
  Top 0.254: MSP430F6779A.67 93.63,86.5 92.13,88 92.13,100.5 88.33,104.33 LCD1.19
S19
  Top 0.254: MSP430F6779A.66 93.88,87 92.63,88.25 92.63,100.75 90.87,102.54 LCD1.20
S20
  Top 0.254: MSP430F6779A.65 94.13,87.5 93.13,88.5 93.13,107.88 LCD1.21
S21
  Top 0.254: MSP430F6779A.64 98.63,107.5 98.13,108 97.94,108.2 95.99,108.2 LCD1.22
S22  (via drill 0.36)
  Top 0.254: MSP430F6779A.63 99.13,108 96.13,111 v95.63,111
  Bottom 0.254: v95.63,111 95.63,137.81 LCD1.23
S23  (via drill 0.36)
  Top 0.254: MSP430F6779A.62 99.63,108.25 95.88,112 v94.63,112
  Bottom 0.254: v94.63,112 94.63,136.9 LCD1.24
S24  (via drill 0.36)
  Top 0.254: MSP430F6779A.61 100.13,108.5 95.63,113 v93.63,113
  Bottom 0.254: v93.63,113 93.63,125 80.71,137.88 LCD1.29
S25  (via drill 0.36)
  Top 0.254: MSP430F6779A.60 100.63,108.75 95.38,114 v92.63,114
  Bottom 0.254: v92.63,114 92.63,125.25 82.38,135.5 80.63,135.5 78.17,137.97 LCD1.30
S26  (via drill 0.36)
  Top 0.254: MSP430F6779A.59 101.13,109 95.13,115 v91.63,115
  Bottom 0.254: v91.63,115 91.63,125.5 82.13,135 78.63,135 75.63,138.01 LCD1.31
S27  (via drill 0.36)
  Top 0.254: MSP430F6779A.58 101.63,109.25 94.88,116 v90.63,116
  Bottom 0.254: v90.63,116 90.63,125.75 81.88,134.5 76.63,134.5 73.09,138.05 LCD1.32
S28  (via drill 0.36)
  Top 0.254: MSP430F6779A.57 102.13,109.5 94.63,117 v89.63,117
  Bottom 0.254: v89.63,117 89.63,126 81.63,134 74.63,134 70.55,138.09 LCD1.33
S29  (via drill 0.36)
  Top 0.254: MSP430F6779A.56 102.63,109.75 94.38,118 v88.63,118
  Bottom 0.254: LCD1.34 72.63,133.5 81.38,133.5 88.63,126.25 v88.63,118
S30  (via drill 0.36)
  Top 0.254: MSP430F6779A.55 103.13,110 94.13,119 v87.63,119
  Bottom 0.254: v87.63,119 87.63,126.5 81.13,133 70.63,133 65.51,138.13 LCD1.35
S31  (via drill 0.36)
  Top 0.254: MSP430F6779A.54 103.63,110.25 93.88,120 v86.63,120
  Bottom 0.254: v86.63,120 86.63,126.75 80.88,132.5 68.63,132.5 63.01,138.13 LCD1.36
S32  (via drill 0.36)
  Top 0.254: MSP430F6779A.53 104.13,110.5 93.63,121 v85.63,121
  Bottom 0.254: v85.63,121 85.63,127 80.63,132 66.63,132 60.51,138.13 LCD1.37
S33  (via drill 0.36)
  Top 0.254: MSP430F6779A.52 104.63,110.75 93.38,122 v84.63,122
  Bottom 0.254: v84.63,122 84.63,127.25 80.38,131.5 64.63,131.5 58.01,138.13 LCD1.38
S34  (via drill 0.36)
  Top 0.254: MSP430F6779A.51 105.13,111 93.13,123 v83.63,123
  Bottom 0.254: v83.63,123 83.63,127.5 80.13,131 62.38,131 55.31,138.08 LCD1.39
S35  (via drill 0.36)
  Top 0.254: MSP430F6779A.50 105.63,111.25 92.88,124 v82.63,124
  Bottom 0.254: v82.63,124 82.63,127.75 79.88,130.5 60.38,130.5 52.77,138.12 LCD1.40
S36  (via drill 0.36)
  Top 0.254: MSP430F6779A.49 106.13,111.5 92.63,125 v81.63,125
  Bottom 0.254: v81.63,125 81.63,128 79.63,130 58.38,130 50.26,138.13 LCD1.41
S37  (via drill 0.36)
  Top 0.254: MSP430F6779A.48 106.63,111.75 92.38,126 v80.63,126
  Bottom 0.254: v80.63,126 80.63,128.25 79.38,129.5 56.38,129.5 47.76,138.13 LCD1.42
S38  (via drill 0.36)
  Top 0.254: MSP430F6779A.47 107.13,112 92.13,127 v79.63,127
  Bottom 0.254: v79.63,127 79.63,128.5 79.13,129 54.38,129 45.26,138.13 LCD1.43
S39  (via drill 0.36)
  Top 0.254: MSP430F6779A.46 107.63,112.25 91.88,128 v78.63,128
  Bottom 0.254: v78.63,128 78.13,128.5 52.13,128.5 42.61,138.03 LCD1.44
SC_INPUT  (via drill 0.6)
  Top 0.813: D6.A 115.63,18.5 v114.63,17.5 | v80.63,11 76.13,11 75.13,12 75.13,28.1 73.93,29.3 D8.C 70.63,27.5 69.94,26.81 C10.1 57.82,26.81 57.13,27.5 SCAP_DC.4 SCAP_DC.3 SCAP_DC.2 SCAP_DC.1
  Bottom 0.813: v114.63,17.5 114.63,17 108.63,11 v80.63,11
SCAP_1
  Top 0.813: D7.C 76.13,30.7 76.13,34.5 75.63,35 R13.1
SMCLK  (via drill 0.2)
  Top 0.254: MSP430F6779A.6 111.13,71.5 v110.63,71
  Bottom 0.254: v110.63,71 112.63,71 113.63,72 113.63,76.5 114.13,77 124.13,77 125.63,78.5 125.63,124.36 CLOCK.5 | CLOCK.5 127.02,125.75 | CLOCK.5 127.24,126
TCK
  Top 0.254: R48.1 17.07,118.03 17.6,118.56 JTG_SEL7.3
  Bottom 0.254: JTG_SEL7.3 18.37,118.56 14.56,122.38 11.38,122.38 JTAG.7
TDI
  Bottom 0.254: JTG_SEL3.3 18.37,123.64 14.51,127.5 11.34,127.5 JTAG.3
TDO
  Top 0.254: JTG_SEL1.3 20.91,124.91 22.82,124.91 23.45,124.28 23.45,117.29 JTG_SELR.1
  Bottom 0.254: JTG_SEL1.3 18.37,126.18 14.56,129.99 11.39,129.99 JTAG.1
TEST/SBWTCK  (via drill 0.2)
  Top 0.254: JTAG.8 14.56,121.73 14.56,113.48 15.83,112.21 18.37,112.21 JTG_SEL8.3 JTG_SEL8.2 22.18,112.45 v23.63,111 | MSP430F6779A.97 94.13,71.5 82.13,83.5 82.13,96 80.13,98 50.63,98 v44.63,104
  Bottom 0.254: v23.63,111 37.63,111 v44.63,104
TMS
  Bottom 0.254: JTG_SEL5.3 18.37,121.1 14.6,124.88 11.42,124.88 JTAG.5
UART_RX  (via drill 0.2)
  Top 0.254: MSP430F6779A.16 121.63,76.5 v128.13,83 | v128.13,113 122.63,118.5 117.63,118.5 116.13,120 116.13,127 114.63,128.5 112.67,128.5 UART.2
  Bottom 0.254: v128.13,83 v128.13,113
UART_TX  (via drill 0.2)
  Top 0.254: MSP430F6779A.17 118.13,77 v126.63,85.5 | v128.13,116.5 128.13,120.5 126.63,122 v117.63,122
  Bottom 0.254: v126.63,85.5 126.63,115 v128.13,116.5 | v117.63,122 117.63,129.5 116.13,131 UART.3
VASYS1/2
  Top 0.254: C23.1 101.13,60.75 100.98,60.6 C22.1 99.63,61.5 102.63,64.5 MSP430F6779A.111 102.63,69 103.13,69.5 107.63,69.5 108.13,69 MSP430F6779A.122 108.13,65.1 109.73,63.5 111.63,63.5 111.87,63.26 C32.1
  Top 0.406: C32.1 111.87,62.26 111.88,62.25 C28.1
VCORE
  Top 0.254: C38.1 112.63,67 112.63,67.2 MSP430F6779A.128
VREF
  Top 0.254: MSP430F6779A.113 103.63,65.25 103.13,64.75 103.13,64 102.63,63.5 C30.1
XIN
  Top 0.254: MSP430F6779A.1 115.13,69 115.98,68.15 117.53,68.15 XT1.P2 119.63,68 120.53,67.1 C37.1 120.53,66.6
XOUT
  Top 0.254: XT1.P1 117.53,70.69 | MSP430F6779A.2 115.13,69.5 116.13,70.5 XT1.P1 | XT1.P1 119.68,70.5 120.49,71.31 120.49,71.96 C40.1

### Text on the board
tNames: CLOCKS | INT | VDSYS | DGND | VCC | DVCC | DVCC | RTCCLK | EXT | RST | TX | ACLK | SYS | VDSYS | RX | MCLK | DGND | SMCLK | J=JTAG | J | S | S=SBW | + | + | + | DVCC LEDS | + | + | + | AGND | AGND | AGND | + | SUPPLY LEDS | + | TIDM-AUX-MODULE | M. MESGANAW / MAY 2014
_tplace: UART | CLOCKS | 1 | INT | VDSYS | DGND | VCC | DVCC | DVCC | RTCCLK | 1 | 2 | 2 | EXT | RST | 3 | TX | ACLK | SYS | VDSYS | RX | 4 | RST_SEL | MCLK | DGND | SMCLK | RESET | 14 | R51 | R48 | R5 | C53 | J=JTAG | J | S | S=SBW | LCD1 | + | LED4 | R61 | JTAG | BTN1 | + | LED3 | R60 | AUX3_HDR | BTN2 | + | G/V | LED2 | R59 | B | * | DVCC LEDS | LED1 | R | + | R58 | AUX3_SEL | D1 | DGND_HDR | R46 | VDSYS_HDR | AUX2_HDR | R8 | C36 | R43 | G/V | C49 | B | * | R42 | R | AUX2_SEL | D3 | MSP430F6779A | AUX1_HDR | CAP1_B | CAP0_A | C43 | C44 | G/V | C40 | B | * | CAP0_B | R | AUX1_SEL | CAP1_A | C38 | XT1 | DVCC_HDR | C34 | R53 | R50 | C35 | CAP1_SEL | C37 | R52 | R49 | C30 | R4 | C31 | C32 | C33 | R10 | C22 | C23 | C29 | C28 | C24 | C25 | C26 | C27 | D2 | DVCC_REG | R11 | CAP0_SEL | R36 | R13 | C8 | AUX3_LED | + | R57 | D7 | A3_LE | R6 | R7 | ZD4 | D8 | R56 | SC_EN | + | EXT_DC | + | C10 | AUX2_LED | V+ | AGND | CB3 | AGND | CBOUT | AGND | CB2 | C5 | A2_LE | + | R55 | DGND | C6 | + | AUX1_LED | GND | - | D6 | A1_LE | SCAP_DC | SUPPLY LEDS | + | R54 | C7 | DVCC_LED | R12 | IC3 | D5 | D_LE | D4 | TIDM-AUX-MODULE | M. MESGANAW / MAY 2014
_bplace: BATT1 | + | + | + | BATT3 | BATT2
